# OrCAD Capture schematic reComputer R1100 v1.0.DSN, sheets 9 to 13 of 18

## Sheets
9 10 USB HUB2 & USB A: size A3
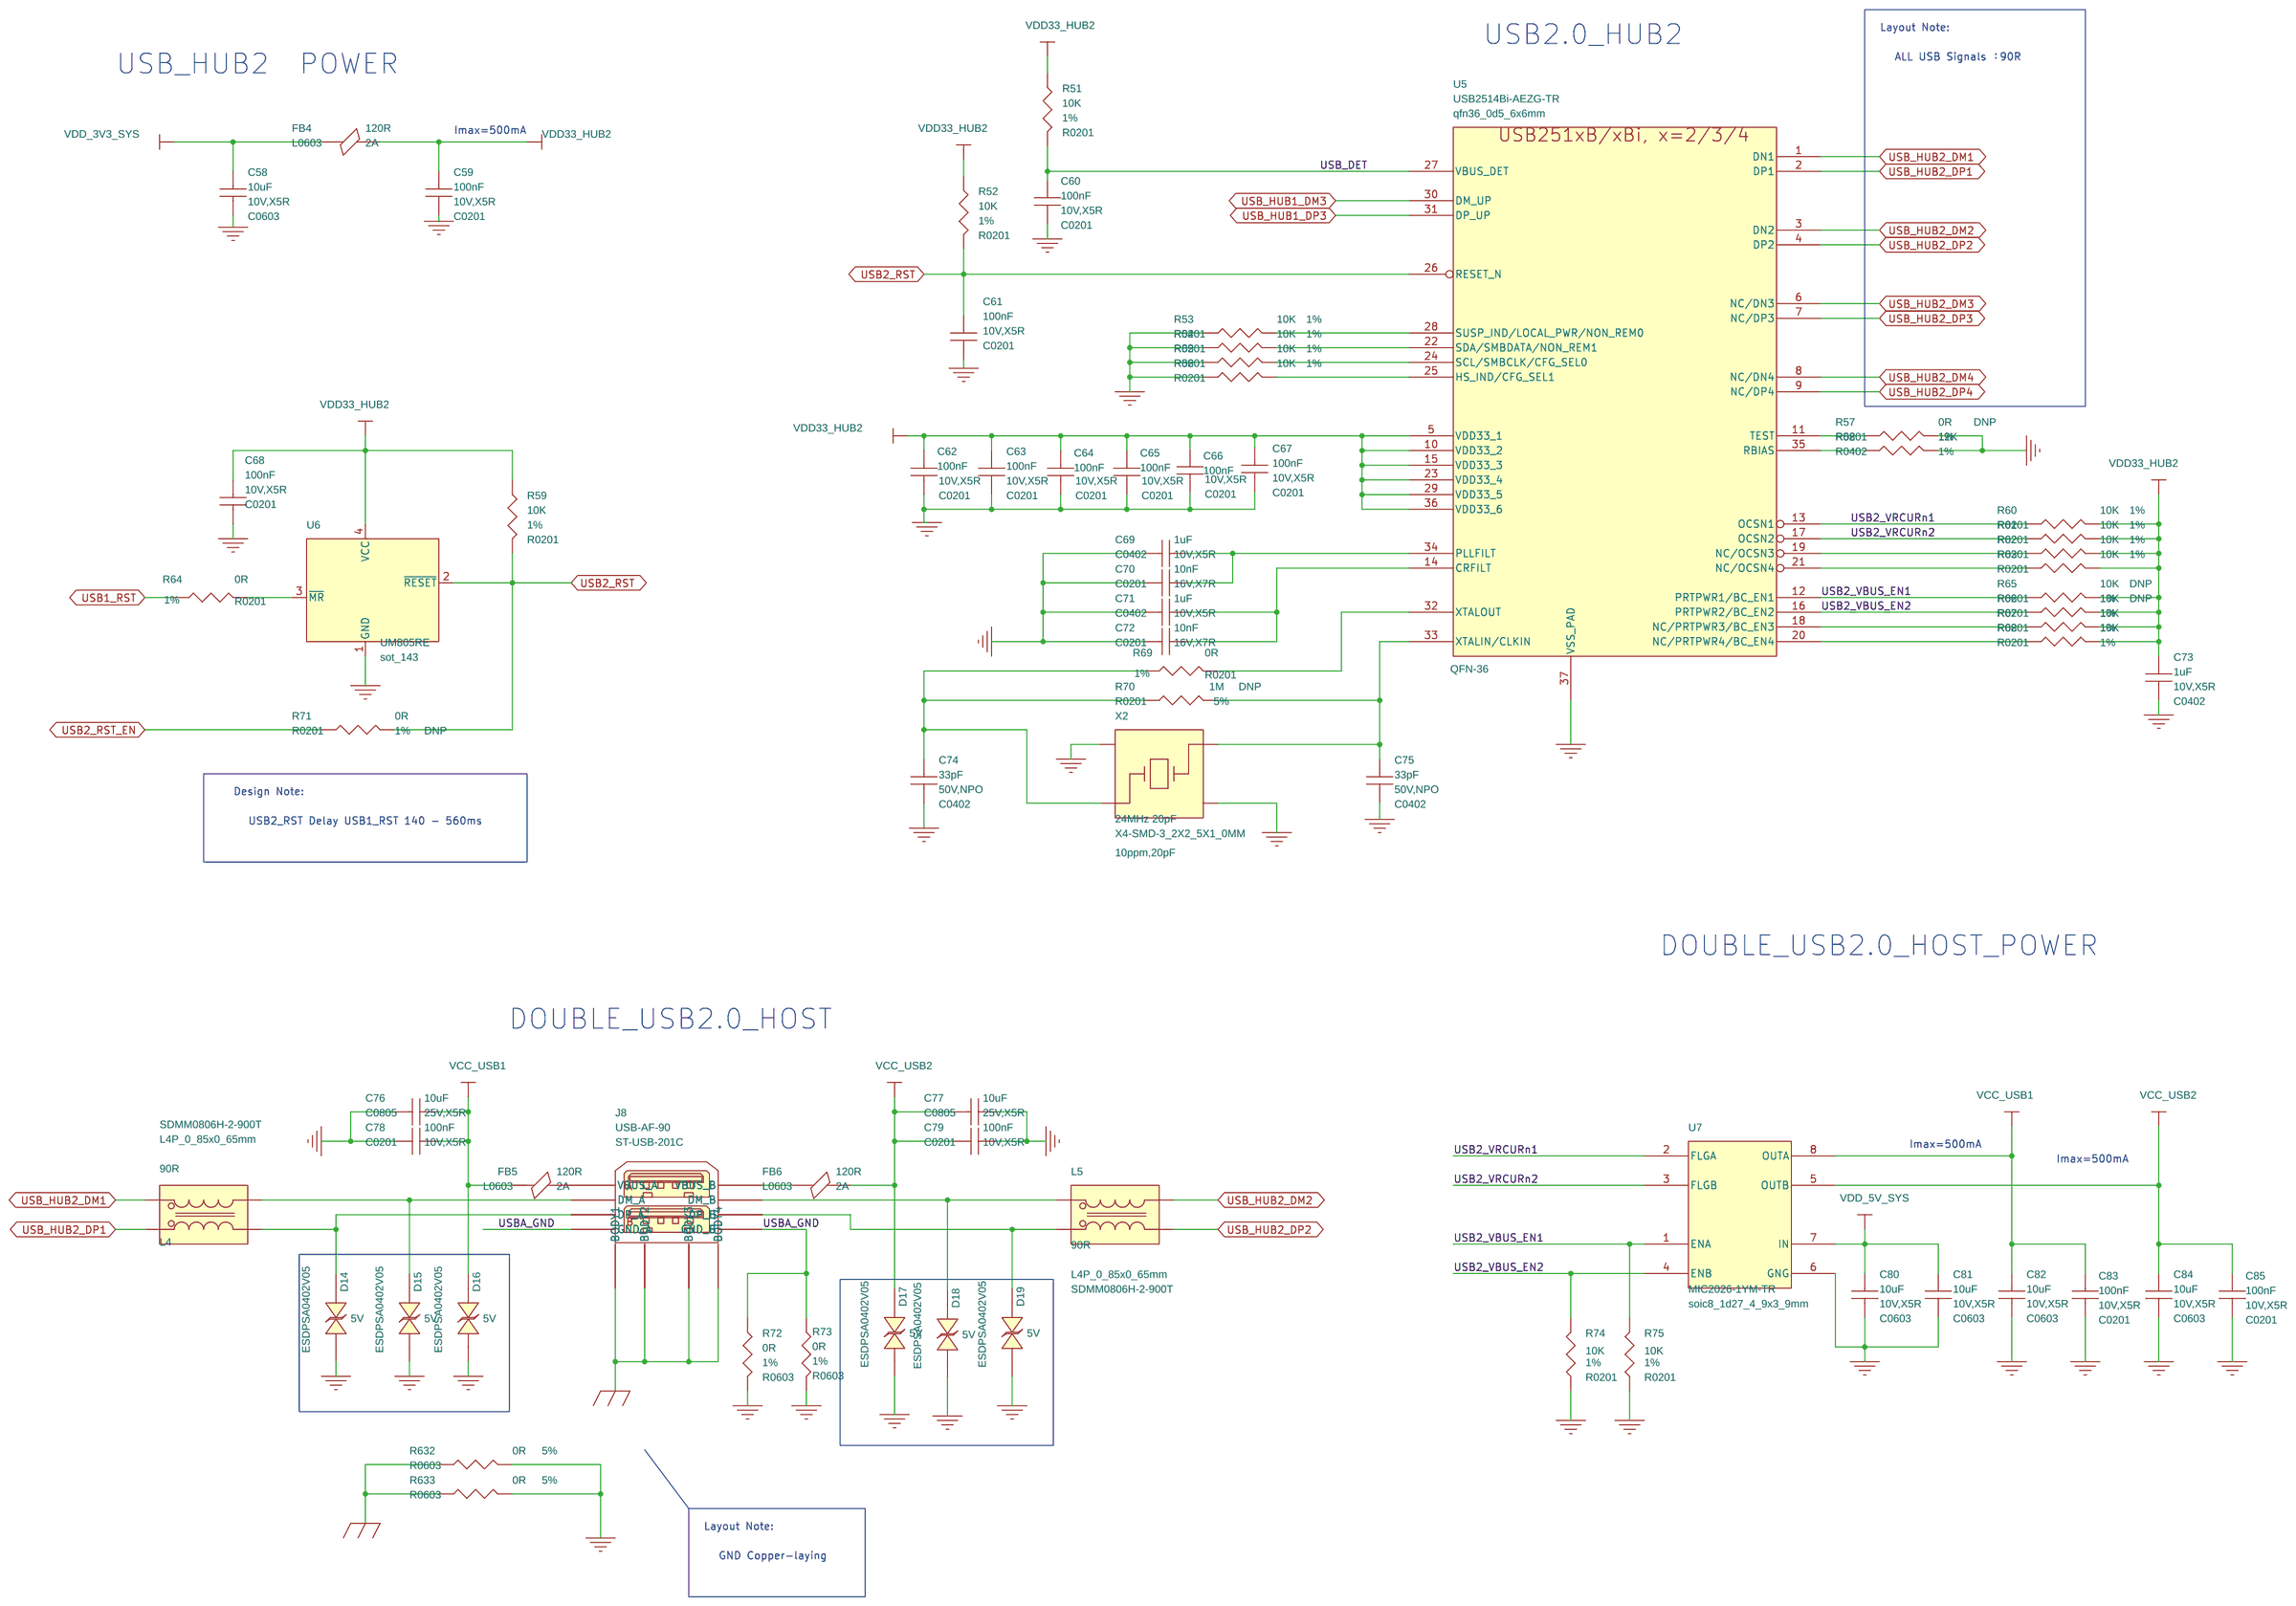
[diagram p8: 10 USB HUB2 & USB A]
10 11 HDMI & CSI0: size A3
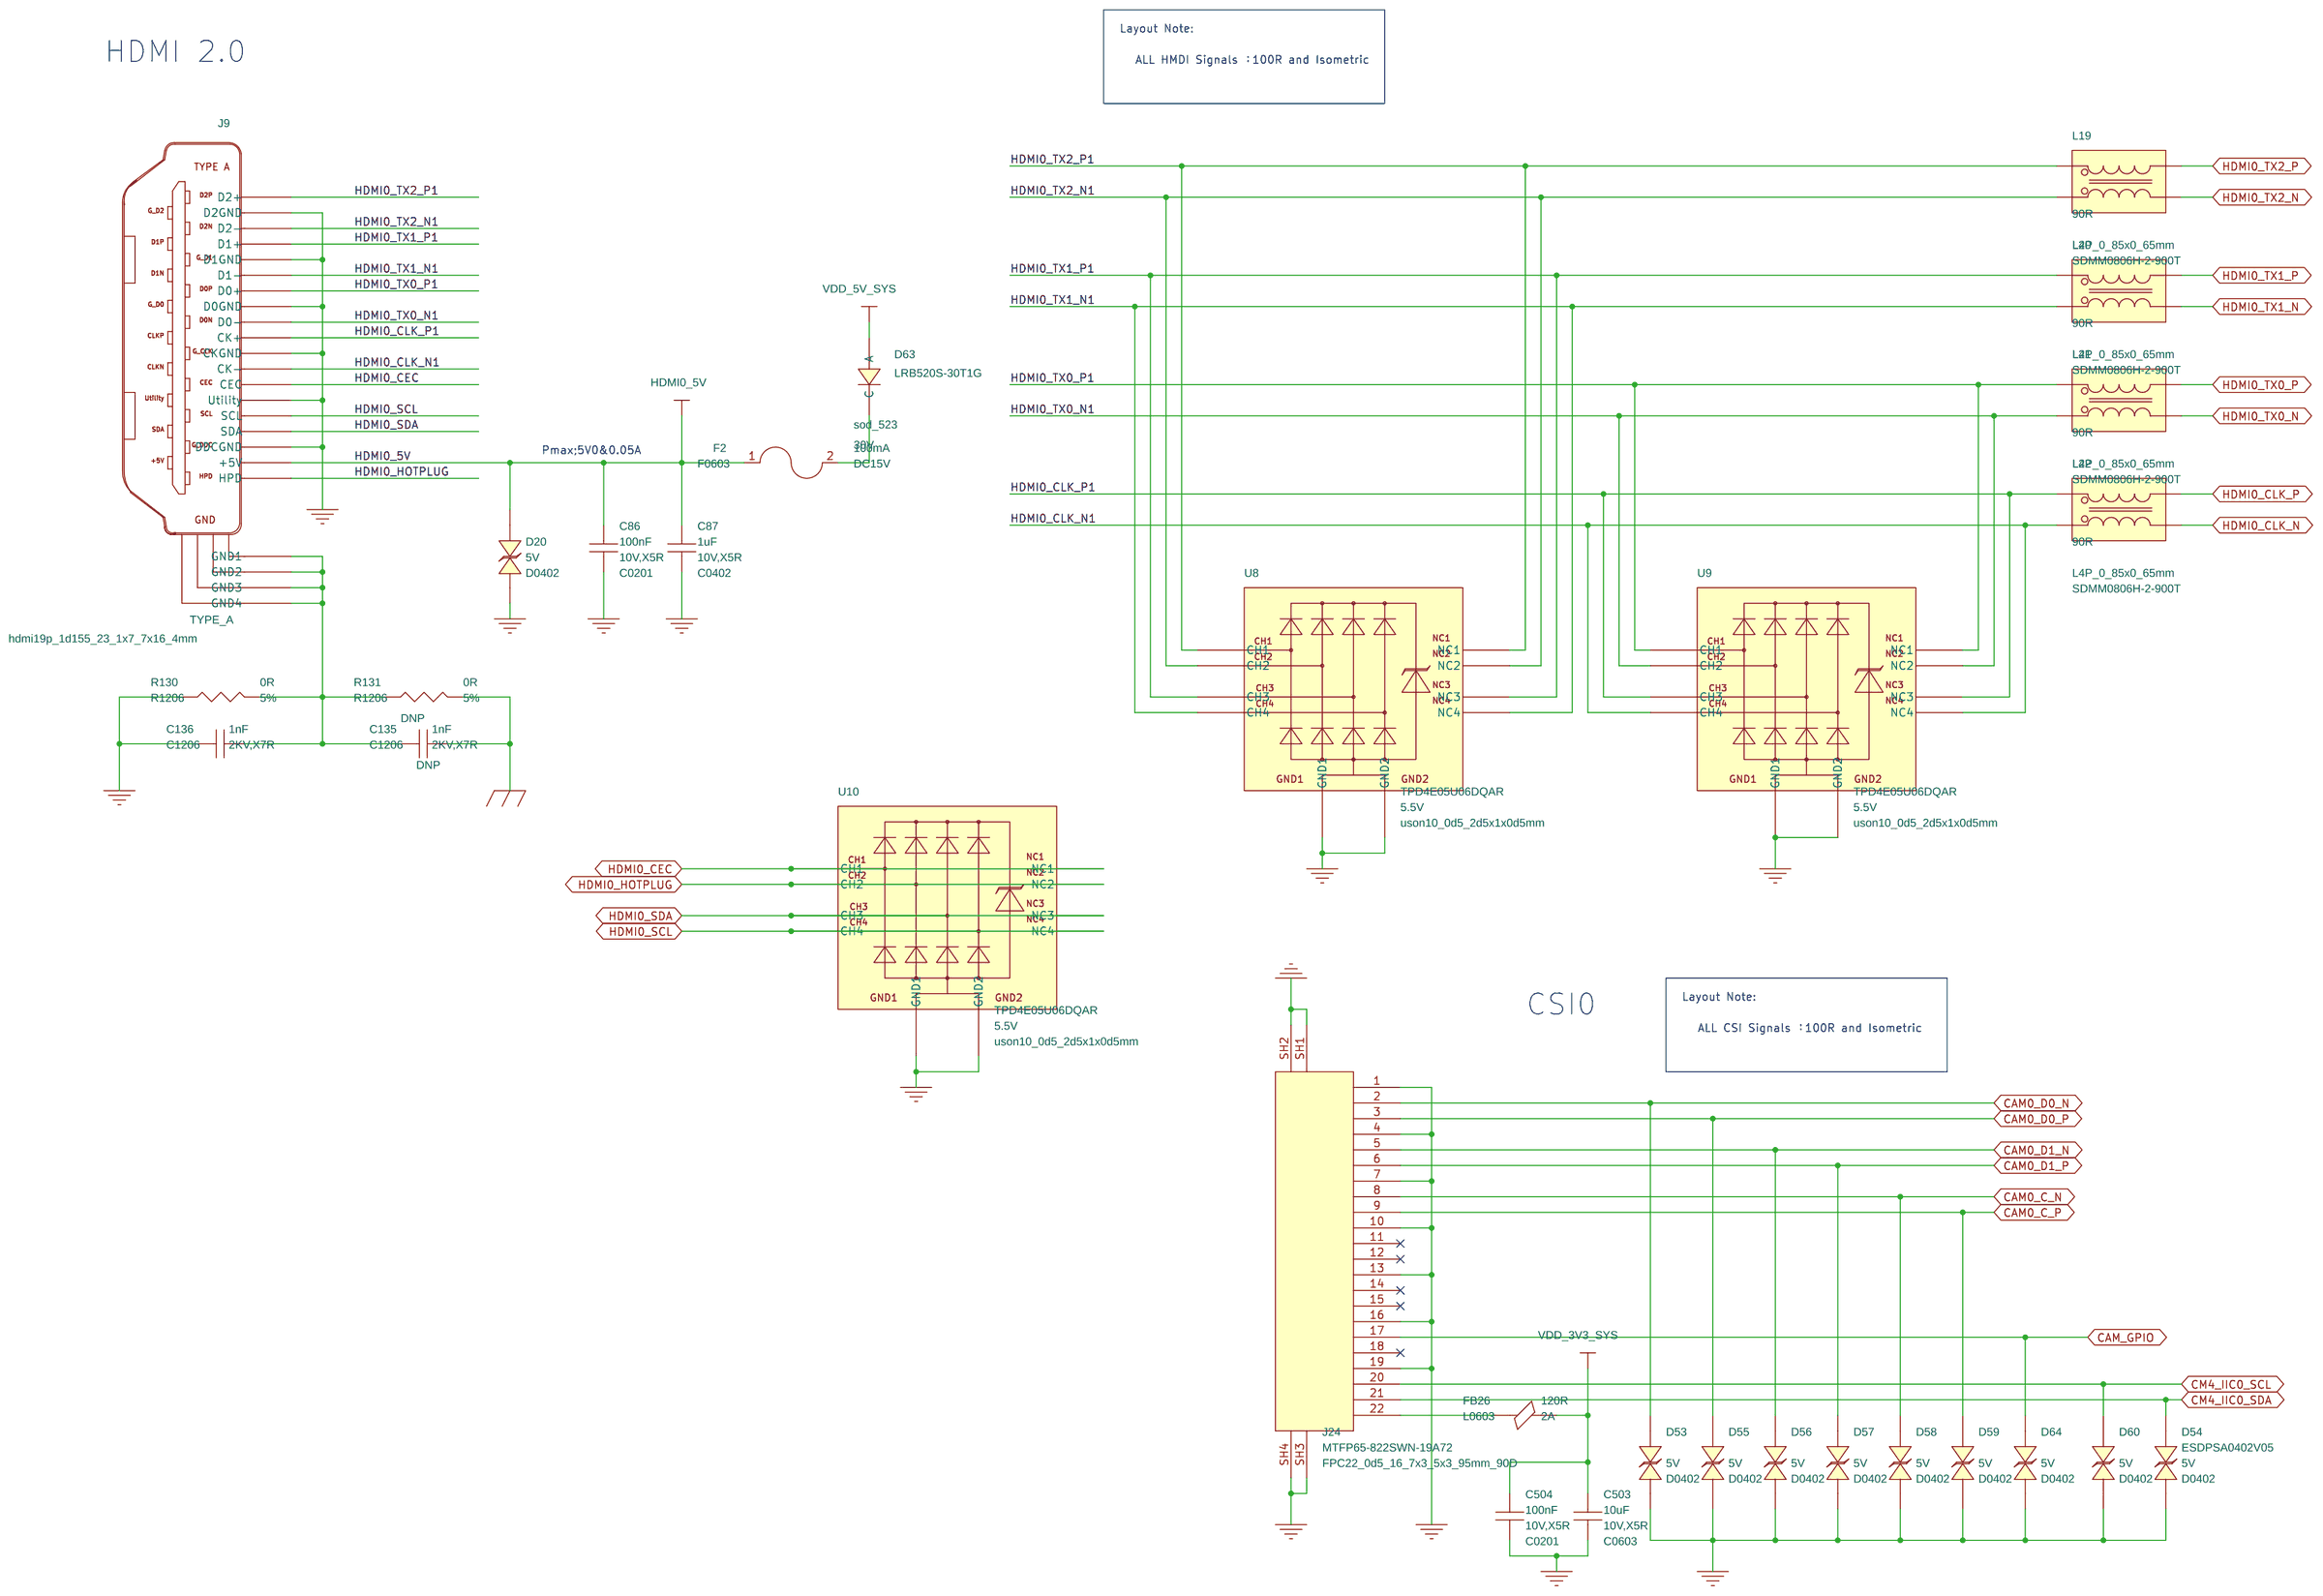
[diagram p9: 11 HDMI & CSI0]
11 13 Type-C Debug: size A3
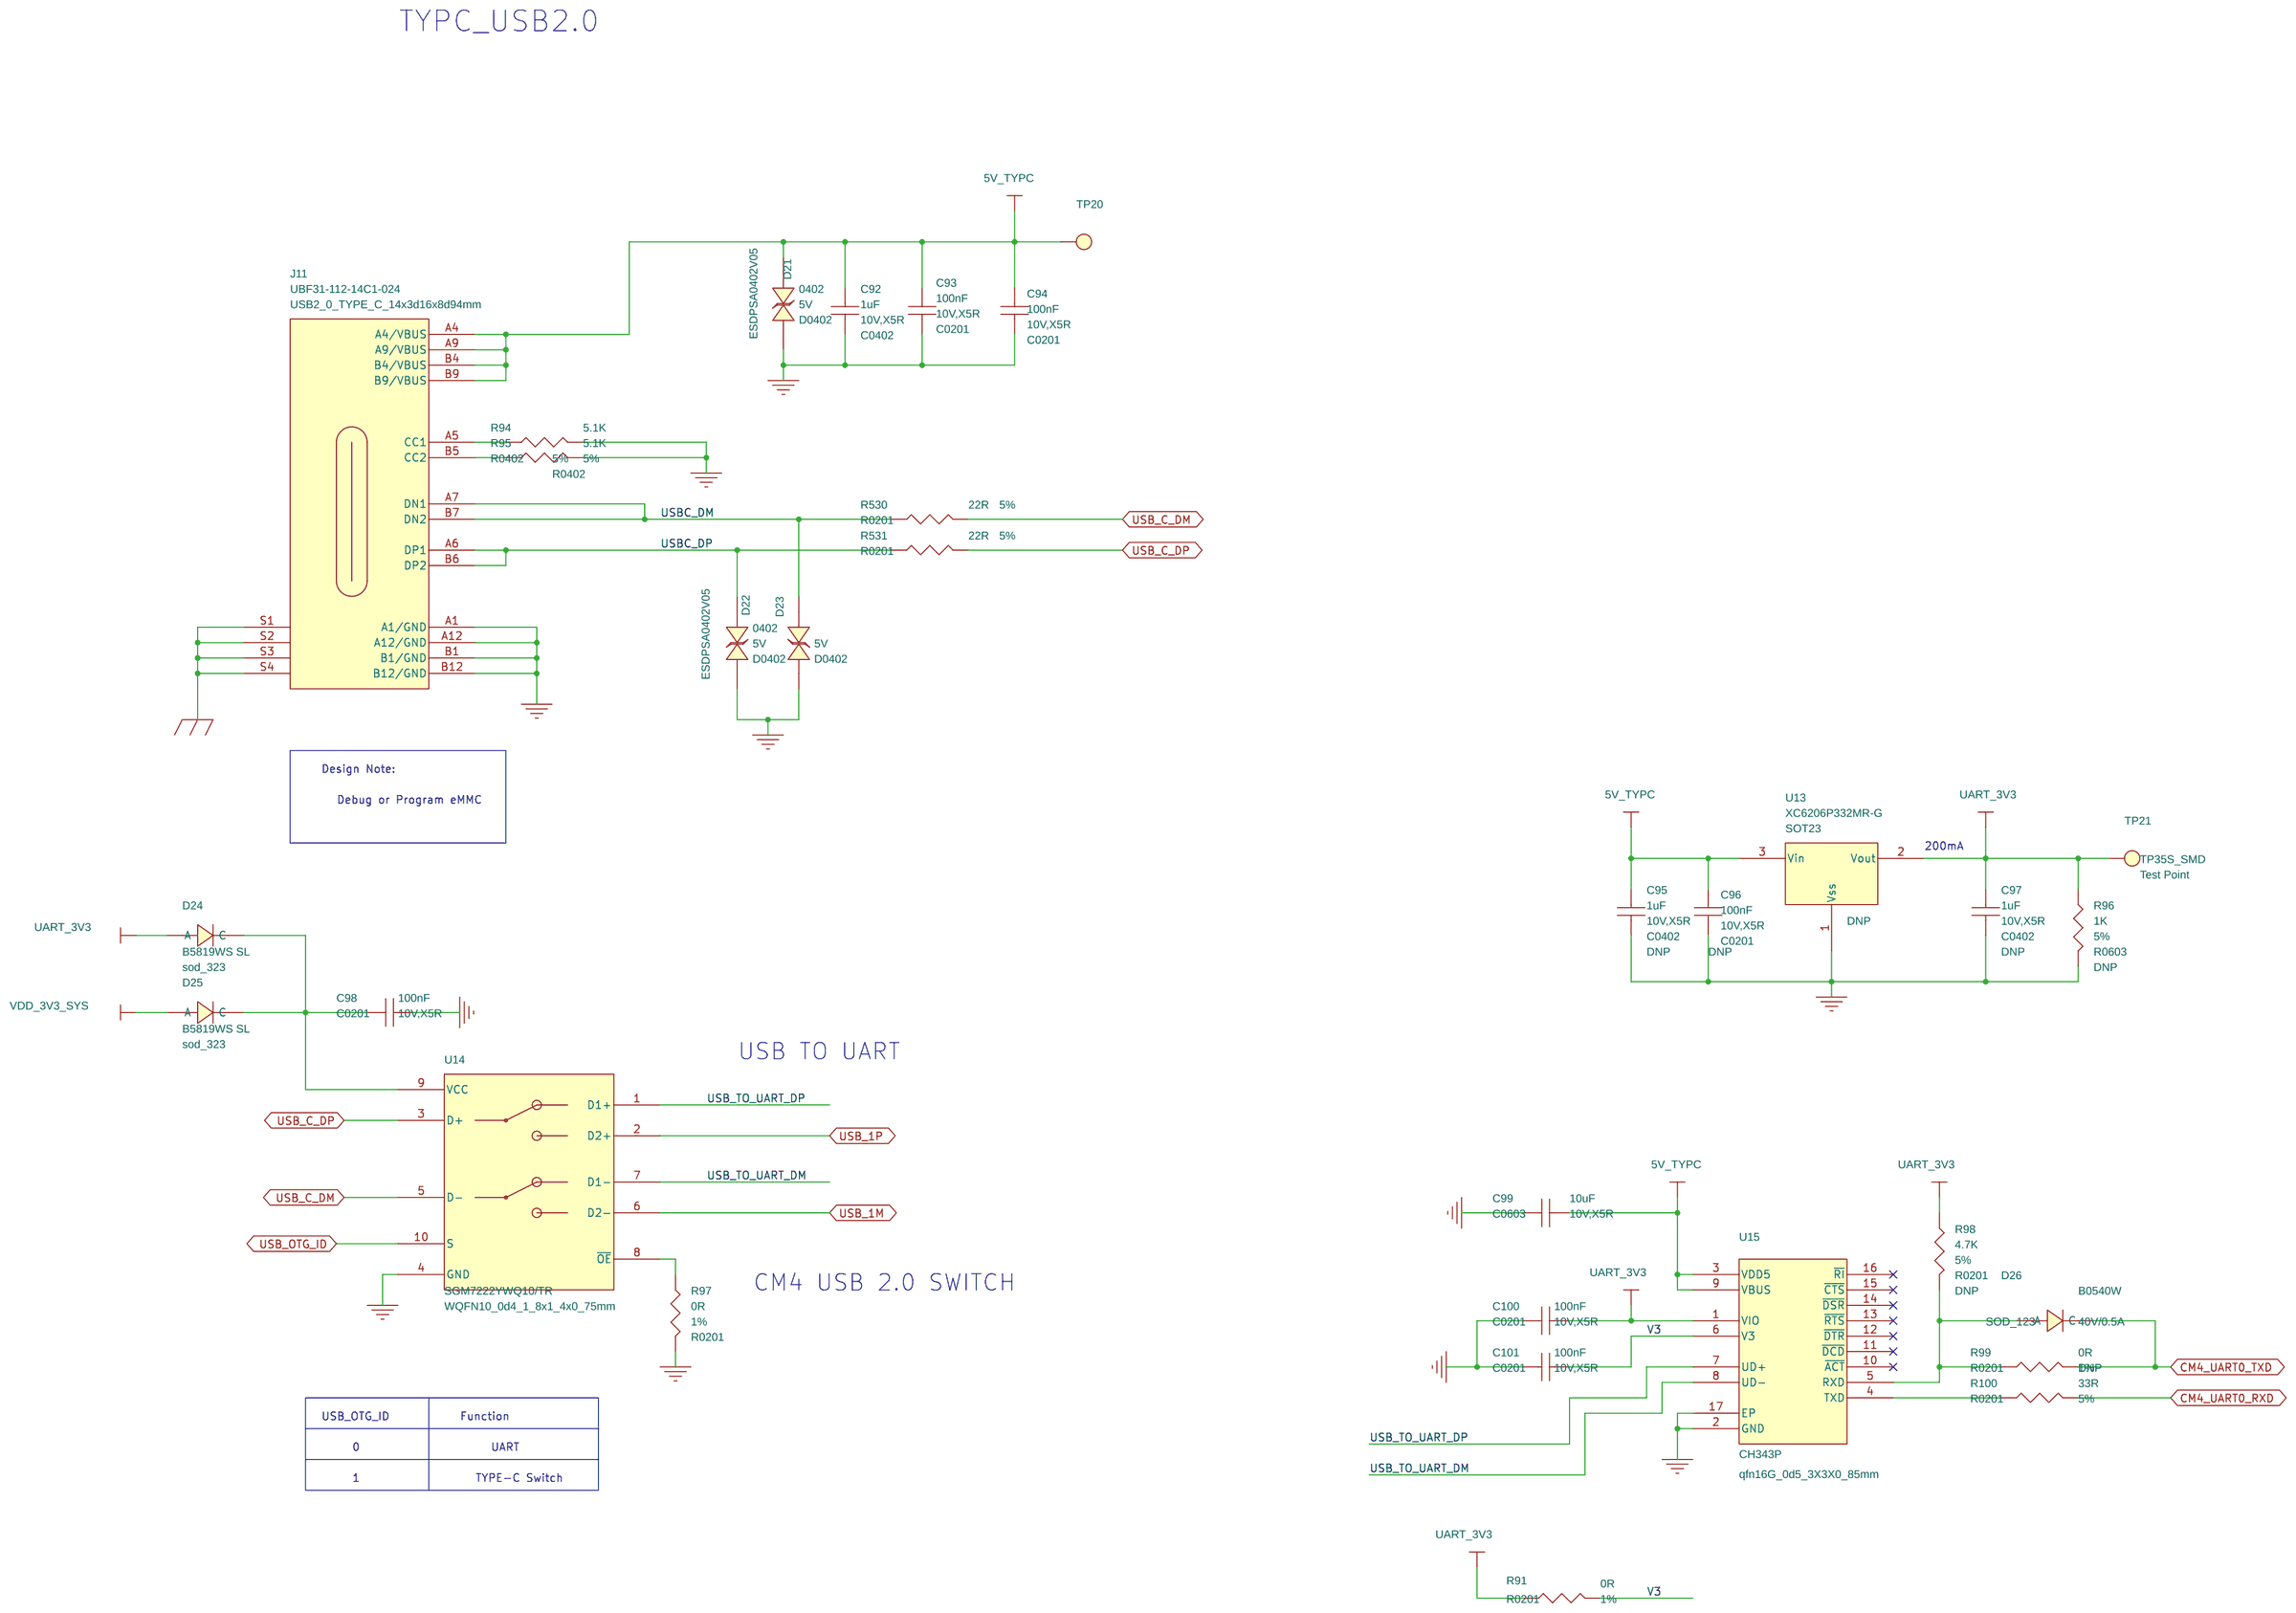
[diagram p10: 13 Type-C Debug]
12 14 RTC & Encryption & EEPROM: size A3
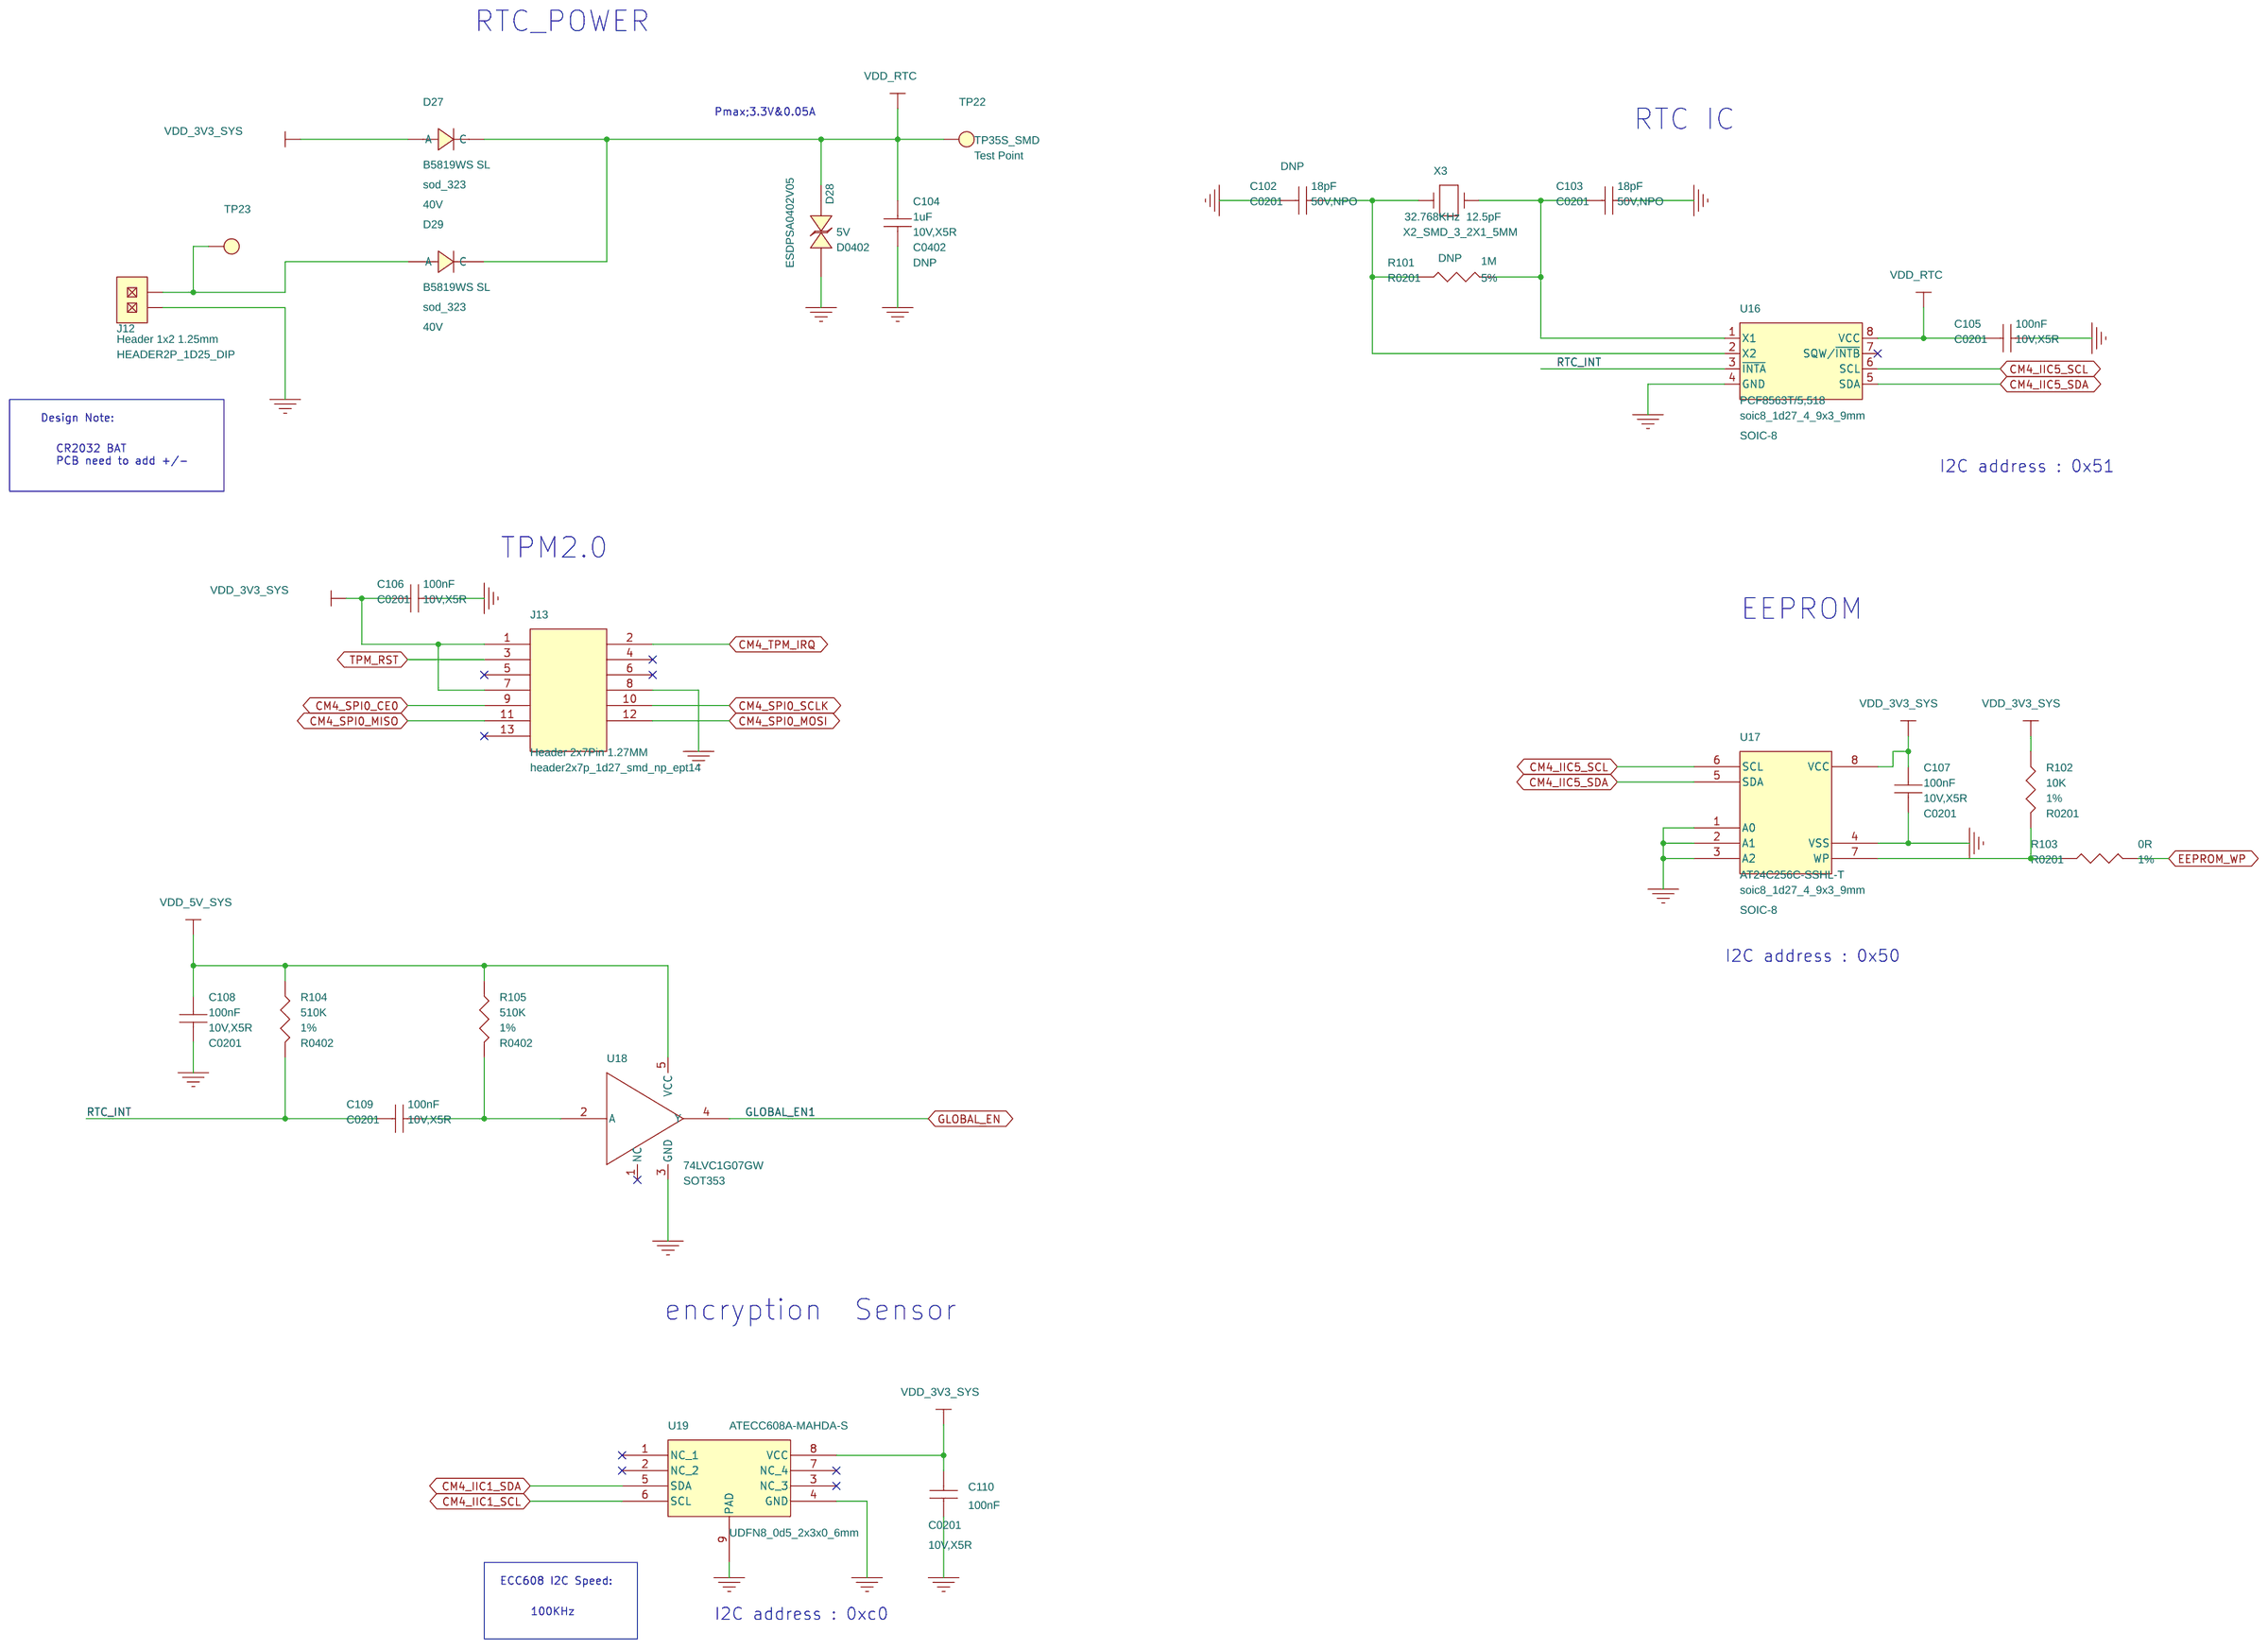
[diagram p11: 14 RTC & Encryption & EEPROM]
13 15 Mini PICe: size A3
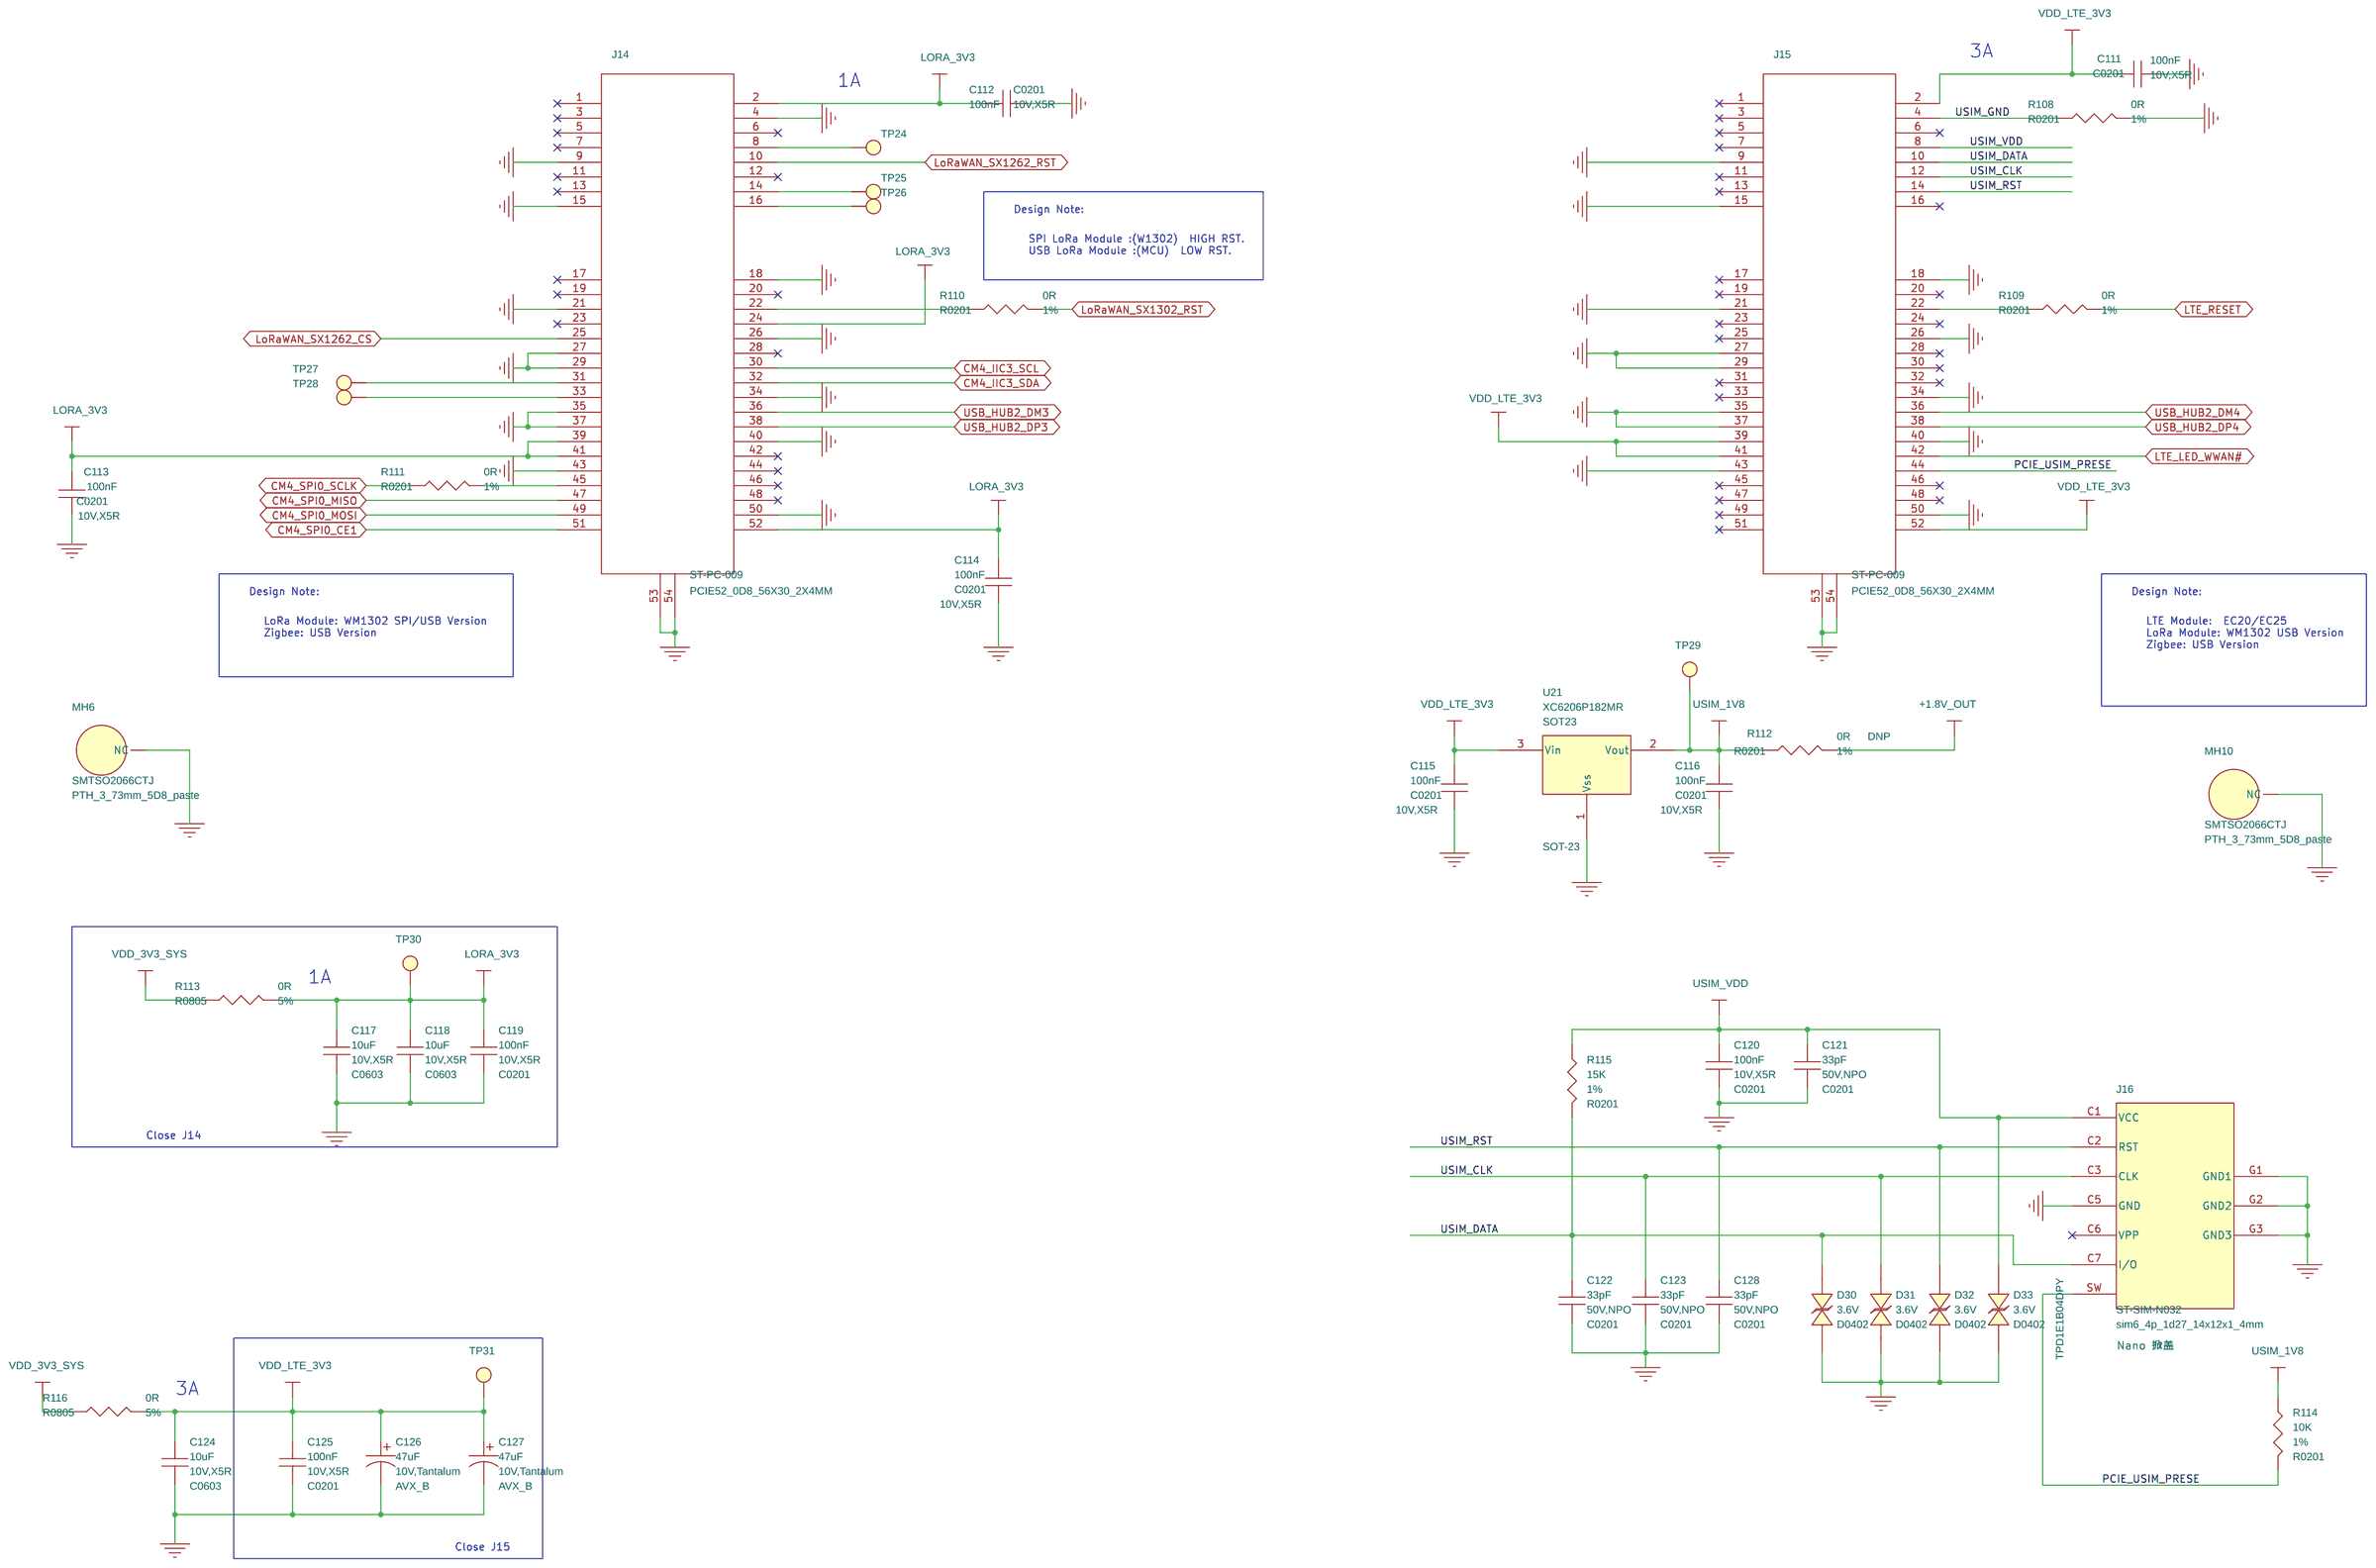
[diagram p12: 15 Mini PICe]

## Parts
sheet 10 USB HUB2 & USB A
C58  10uF  [C0603]
C59  100nF  [C0201]
C60  100nF  [C0201]
C61  100nF  [C0201]
C62  100nF  [C0201]
C63  100nF  [C0201]
C64  100nF  [C0201]
C65  100nF  [C0201]
C66  100nF  [C0201]
C67  100nF  [C0201]
C68  100nF  [C0201]
C69  1uF  [C0402]
C70  10nF  [C0201]
C71  1uF  [C0402]
C72  10nF  [C0201]
C73  1uF  [C0402]
C74  33pF  [C0402]
C75  33pF  [C0402]
C76  10uF  [C0805]
C77  10uF  [C0805]
C78  100nF  [C0201]
C79  100nF  [C0201]
C80  10uF  [C0603]
C81  10uF  [C0603]
C82  10uF  [C0603]
C83  100nF  [C0201]
C84  10uF  [C0603]
C85  100nF  [C0201]
D14  ESDPSA0402V05  [D0402]
D15  ESDPSA0402V05  [D0402]
D16  ESDPSA0402V05  [D0402]
D17  ESDPSA0402V05  [D0402]
D18  ESDPSA0402V05  [D0402]
D19  ESDPSA0402V05  [D0402]
FB4  120R  [L0603]
FB5  120R  [L0603]
FB6  120R  [L0603]
J8  USB-AF-90  [ST-USB-201C]
L4  90R  [L4P_0_85x0_65mm]
L5  90R  [L4P_0_85x0_65mm]
R51  10K  [R0201]
R52  10K  [R0201]
R53  10K  [R0201]
R54  10K  [R0201]
R55  10K  [R0201]
R56  10K  [R0201]
R57  0R  [R0201]
R58  12K  [R0402]
R59  10K  [R0201]
R60  10K  [R0201]
R61  10K  [R0201]
R62  10K  [R0201]
R63  10K  [R0201]
R64  0R  [R0201]
R65  10K  [R0201]
R66  10K  [R0201]
R67  10K  [R0201]
R68  10K  [R0201]
R69  0R  [R0201]
R70  1M  [R0201]
R71  0R  [R0201]
R72  0R  [R0603]
R73  0R  [R0603]
R74  10K  [R0201]
R75  10K  [R0201]
R632  0R  [R0603]
R633  0R  [R0603]
U5  USB2514Bi-AEZG-TR  [qfn36_0d5_6x6mm]
U6  UM805RE  [sot_143]
U7  MIC2026-1YM-TR  [soic8_1d27_4_9x3_9mm]
X2  24MHz 20pF  [X4-SMD-3_2X2_5X1_0MM]
sheet 11 HDMI & CSI0
C86  100nF  [C0201]
C87  1uF  [C0402]
C135  1nF  [C1206]
C136  1nF  [C1206]
C503  10uF  [C0603]
C504  100nF  [C0201]
D20  ESDPSA0402V05  [D0402]
D53  ESDPSA0402V05  [D0402]
D54  ESDPSA0402V05  [D0402]
D55  ESDPSA0402V05  [D0402]
D56  ESDPSA0402V05  [D0402]
D57  ESDPSA0402V05  [D0402]
D58  ESDPSA0402V05  [D0402]
D59  ESDPSA0402V05  [D0402]
D60  ESDPSA0402V05  [D0402]
D63  LRB520S-30T1G  [sod_523]
D64  ESDPSA0402V05  [D0402]
F2  100mA  [F0603]
FB26  120R  [L0603]
J9  TYPE_A  [hdmi19p_1d155_23_1x7_7x16_4mm]
J24  MTFP65-822SWN-19A72  [FPC22_0d5_16_7x3_5x3_95mm_90D]
L19  90R  [L4P_0_85x0_65mm]
L20  90R  [L4P_0_85x0_65mm]
L21  90R  [L4P_0_85x0_65mm]
L22  90R  [L4P_0_85x0_65mm]
R130  0R  [R1206]
R131  0R  [R1206]
U8  TPD4E05U06DQAR  [uson10_0d5_2d5x1x0d5mm]
U9  TPD4E05U06DQAR  [uson10_0d5_2d5x1x0d5mm]
U10  TPD4E05U06DQAR  [uson10_0d5_2d5x1x0d5mm]
sheet 13 Type-C Debug
C92  1uF  [C0402]
C93  100nF  [C0201]
C94  100nF  [C0201]
C95  1uF  [C0402]
C96  100nF  [C0201]
C97  1uF  [C0402]
C98  100nF  [C0201]
C99  10uF  [C0603]
C100  100nF  [C0201]
C101  100nF  [C0201]
D21  ESDPSA0402V05  [D0402]
D22  ESDPSA0402V05  [D0402]
D23  ESDPSA0402V05  [D0402]
D24  B5819WS SL  [sod_323]
D25  B5819WS SL  [sod_323]
D26  B0540W  [SOD_123]
J11  UBF31-112-14C1-024  [USB2_0_TYPE_C_14x3d16x8d94mm]
R91  0R  [R0201]
R94  5.1K  [R0402]
R95  5.1K  [R0402]
R96  1K  [R0603]
R97  0R  [R0201]
R98  4.7K  [R0201]
R99  0R  [R0201]
R100  33R  [R0201]
R530  22R  [R0201]
R531  22R  [R0201]
TP20  Test Point  [TP35S_SMD]
TP21  Test Point  [TP35S_SMD]
U13  XC6206P332MR-G  [SOT23]
U14  SGM7222YWQ10/TR  [WQFN10_0d4_1_8x1_4x0_75mm]
U15  CH343P  [qfn16G_0d5_3X3X0_85mm]
sheet 14 RTC & Encryption & EEPROM
C102  18pF  [C0201]
C103  18pF  [C0201]
C104  1uF  [C0402]
C105  100nF  [C0201]
C106  100nF  [C0201]
C107  100nF  [C0201]
C108  100nF  [C0201]
C109  100nF  [C0201]
C110  100nF  [C0201]
D27  B5819WS SL  [sod_323]
D28  ESDPSA0402V05  [D0402]
D29  B5819WS SL  [sod_323]
J12  Header 1x2 1.25mm  [HEADER2P_1D25_DIP]
J13  Header 2x7Pin 1.27MM  [header2x7p_1d27_smd_np_ept14]
R101  1M  [R0201]
R102  10K  [R0201]
R103  0R  [R0201]
R104  510K  [R0402]
R105  510K  [R0402]
TP22  Test Point  [TP35S_SMD]
TP23  Test Point  [TP35S_SMD]
U16  PCF8563T/5,518  [soic8_1d27_4_9x3_9mm]
U17  AT24C256C-SSHL-T  [soic8_1d27_4_9x3_9mm]
U18  74LVC1G07GW  [SOT353]
U19  ATECC608A-MAHDA-S  [UDFN8_0d5_2x3x0_6mm]
X3  32.768KHz  12.5pF  [X2_SMD_3_2X1_5MM]
sheet 15 Mini PICe
C111  100nF  [C0201]
C112  100nF  [C0201]
C113  100nF  [C0201]
C114  100nF  [C0201]
C115  100nF  [C0201]
C116  100nF  [C0201]
C117  10uF  [C0603]
C118  10uF  [C0603]
C119  100nF  [C0201]
C120  100nF  [C0201]
C121  33pF  [C0201]
C122  33pF  [C0201]
C123  33pF  [C0201]
C124  10uF  [C0603]
C125  100nF  [C0201]
C126  47uF  [AVX_B]
C127  47uF  [AVX_B]
C128  33pF  [C0201]
D30  TPD1E1B04DPY  [D0402]
D31  TPD1E1B04DPY  [D0402]
D32  TPD1E1B04DPY  [D0402]
D33  TPD1E1B04DPY  [D0402]
J14  ST-PC-009  [PCIE52_0D8_56X30_2X4MM]
J15  ST-PC-009  [PCIE52_0D8_56X30_2X4MM]
J16  ST-SIM-N032  [sim6_4p_1d27_14x12x1_4mm]
MH6  SMTSO2066CTJ  [PTH_3_73mm_5D8_paste]
MH10  SMTSO2066CTJ  [PTH_3_73mm_5D8_paste]
R108  0R  [R0201]
R109  0R  [R0201]
R110  0R  [R0201]
R111  0R  [R0201]
R112  0R  [R0201]
R113  0R  [R0805]
R114  10K  [R0201]
R115  15K  [R0201]
R116  0R  [R0805]
TP24  Test Point  [TP35S_SMD]
TP25  Test Point  [TP35S_SMD]
TP26  Test Point  [TP35S_SMD]
TP27  Test Point  [TP35S_SMD]
TP28  Test Point  [TP35S_SMD]
TP29  Test Point  [TP35S_SMD]
TP30  Test Point  [TP35S_SMD]
TP31  Test Point  [TP35S_SMD]
U21  XC6206P182MR  [SOT23]

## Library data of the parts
C58 = CC: SMD CAP Ceramic 10uF-10V-10%-X5R;0603; CLASS: DISCRETE; Company Part Status: BeagleBone Carrier Board; Dielectric Type: Ceramic; Manufacturer: YAGEO; Manufacturer PN: CC0603KRX5R6BB106; Manufacturer Part Number: CC0603KRX5R6BB106; PN: 302010103; Package Size: 0603; Part Type: Ceramic; Rating: 10V,X5R; Status: BeagleBone Carrier Board; Temperature: -55°C to 85°C; Temperature Coefficient: X5R; Tolerance: 10%
C59-C68 C83 C85 C93 C94 C98 C100 C101 C111 C119 C125 C504 = CC: SMD CAP Ceramic 100nF-10V-10%-X5R;0201; CLASS: DISCRETE; Company Part Status: BeagleBone Carrier Board; Dielectric Type: Ceramic; Manufacturer: YAGEO; Manufacturer PN: CC0402KRX7R8BB104; Manufacturer Part Number: CC0201KRX5R6BB104; PN: 302010271; Package Size: 0201; Part Type: Ceramic; Rating: 10V,X5R; SIGNAL_MODEL: DEFAULT_CAPACITOR_100000pF_1_2; Status: ODYSSEY-i.MX8M; Temperature: -55°C to 85°C; Temperature Coefficient: X7R; Tolerance: 10%
C69 C71 C73 = CC: SMD CAP Ceramic 1uF-10V-10%-X5R;0402; CLASS: DISCRETE; Company Part Status: BeagleBone Carrier Board; Dielectric Type: Ceramic; Manufacturer: YAGEO; Manufacturer PN: CC0402KRX5R6BB105; Manufacturer Part Number: CC0402KRX5R6BB105; PN: 302010040; Package Size: 0402; Part Type: Ceramic; Rating: 10V,X5R; Status: BeagleBone Carrier Board; Temperature: -55°C to 85°C; Temperature Coefficient: X5R; Tolerance: 10%
C70 C72 = CC: SMD CAP Ceramic 10nF-16V-10%-X7R;0201; CLASS: DISCRETE; Company Part Status: BeagleBone Carrier Board; Dielectric Type: Ceramic; Manufacturer: YAGEO; Manufacturer PN: CC0402KRX7R9BB103; Manufacturer Part Number: CC0201KRX7R7BB103; PN: 302010431; Part Type: Ceramic; Rating: 16V,X7R; SIGNAL_MODEL: DEFAULT_CAPACITOR_10000pF_1_2; Status: BeagleBone AI TDA4VM; Temperature: -55°C to 125°C; Temperature Coefficient: X7R; Tolerance: 10%
C74 C75 = CC: SMD CAP Ceramic 33pF-50V-1%-NPO;0402; Manufacturer: Murata; Manufacturer Part Number: GRM1555C1H330FA01D; PN: 302012253; Package Size: 0402; Rating: 50V,NPO; Status: reComputer R1000; Temperature: -55°C to 125°C
C76 C77 = CC: SMD CAP Ceramic 10uF-25V-10%-X5R;0805; CLASS: DISCRETE; Dielectric Type: Ceramic; Manufacturer: YAGEO; Manufacturer PN: CC0603MRX5R6BB226; Manufacturer Part Number: CC0805KKX5R8BB106; PN: 302010178; Package Size: 0603; Part Type: Ceramic; Rating: 25V,X5R; Status: BeagleBone Carrier Board; Temperature: -55°C to 85°C; Temperature Coefficient: X5R; Tolerance: 20%
C78 C79 = CC: SMD CAP Ceramic 100nF-10V-10%-X5R;0201; CLASS: DISCRETE; Company Part Status: BeagleBone Carrier Board; Dielectric Type: Ceramic; Manufacturer: YAGEO; Manufacturer PN: CC0402KRX7R8BB104; Manufacturer Part Number: CC0201KRX5R6BB104; PN: 302010271; Package Size: 0201; Part Type: Ceramic; Rating: 10V,X5R; Status: ODYSSEY-i.MX8M; Temperature: -55°C to 85°C; Temperature Coefficient: X7R; Tolerance: 10%
C80-C82 C84 C99 C117 C118 C124 = CC: SMD CAP Ceramic 10uF-10V-10%-X5R;0603; CLASS: DISCRETE; Dielectric Type: Ceramic; Manufacturer: YAGEO; Manufacturer PN: CC0603MRX5R6BB226; Manufacturer Part Number: CC0603KRX5R6BB106; PN: 302010103; Package Size: 0603; Part Type: Ceramic; Rating: 10V,X5R; Status: BeagleBone Carrier Board; Temperature: -55°C to 85°C; Temperature Coefficient: X5R; Tolerance: 20%
D14-D23 D28 = DIODE_TVS_BI-DIR: SMD Diode ESD 0.05pF;0402; CLASS: DISCRETE; Company Part Status: BeagleBone Carrier Board; Manufacturer: SEMITEL; PN: 304060074; Package Size: 0402; Part Type: TVS; Rated Voltage: 5V; Rating: 5V; Status: BeagleBone Carrier Board; Temperature: -40°C to 90°C
FB4-FB6 FB26 = FB: SMD Ferrite Bead;120R-2A;0603; CLASS: DISCRETE; Company Part Status: BeagleBone Carrier Board; Manufacturer: Murata; Manufacturer PN: BLM18PG121SN1D; Manufacturer Part Number: BLM18PG121SN1D; PN: 303030024; Package Size: 0603; Part Type: Ferrite Bead; Rating: 2A; Status: BeagleBone Carrier Board; Temperature: -55°C to 125°C
J8 = Dual_USB_A: DIP USB FEMAL TYPE A;8P-2.0-90D; Manufacturer: 宇亮; PN: 320010475; Part Type: USB; Status: BeagleBone Carrier Board
L4 L5 L19-L22 = CL: SMD Common Mode Filter 90R-100mA;4P-L0.85*W0.65*H0.40mm; Manufacturer: Sunlord; Manufacturer Part Number: SDMM0806H-2-900T; PN: 303050463; Package Size: 0.85x0.65 mm; Status: BeaglePlay; Temperature: -40°C to 85°C
R51-R56 R59 R102 = R: SMD RES 10K-±1%-1/20W;0201; CLASS: DISCRETE; Company Part Status: BeagleBone Carrier Board; Manufacturer: YAGEO; Manufacturer PN: RC0402JR-0710KL; Manufacturer Part Number: RC0201FR-0710KL; PN: 301010526; Package Size: 0201; Part Type: RES; Rated Power: 1/16W; Rating: 1%; Status: BeagleBone AI TDA4VM; Temperature: -55°C to 125°C
R57 R112 = R: SMD RES 0R-±1%-1/20W;0201; ASSY: DNP; CLASS: DISCRETE; Company Part Status: BeagleBone Carrier Board; Manufacturer: YAGEO; Manufacturer PN: RC0402JR-070RL; Manufacturer Part Number: RC0201FR-070RL; PN: 301010525; Package Size: 0201; Part Type: RES; Rated Power: 1/16W; Rating: 1%; SIGNAL_MODEL: DEFAULT_RESISTOR_0.001OHM_1_2; Status: BeagleBone AI TDA4VM; Temperature: -55°C to 125°C; Datasheet: Y:\01_Cadence_Library\05_Datasheet\301010000_YAGEO_RC0402JR-070RL_Datasheet.pdf
R58 = R: SMD RES 12K-1%-1/16W;0402; CLASS: DISCRETE; Company Part Status: BeagleBone Carrier Board; Manufacturer: YAGEO; Manufacturer PN: RC0402FR-0712KL; Manufacturer Part Number: RC0402FR-0712KL; PN: 301010736; Package Size: 0402; Part Type: RES; Rated Power: 1/16W; Rating: 1%; SIGNAL_MODEL: DEFAULT_RESISTOR_12000OHM_1_2; Status: BeagleBone Carrier Board; Temperature: -55°C to 155°C
R60-R63 R67 R68 R74 R75 = R: SMD RES 10K-±1%-1/20W;0201; CLASS: DISCRETE; Company Part Status: BeagleBone Carrier Board; Manufacturer: YAGEO; Manufacturer PN: RC0402JR-0710KL; Manufacturer Part Number: RC0201FR-0710KL; PN: 301010526; Package Size: 0201; Part Type: RES; Rated Power: 1/16W; Rating: 1%; SIGNAL_MODEL: DEFAULT_RESISTOR_10000OHM_1_2; Status: BeagleBone AI TDA4VM; Temperature: -55°C to 125°C
R64 R69 R103 = R: SMD RES 0R-±1%-1/20W;0201; CLASS: DISCRETE; Company Part Status: BeagleBone Carrier Board; Manufacturer: YAGEO; Manufacturer PN: RC0402JR-070RL; Manufacturer Part Number: RC0201FR-070RL; PN: 301010525; Package Size: 0201; Part Type: RES; Rated Power: 1/16W; Rating: 1%; Status: BeagleBone AI TDA4VM; Temperature: -55°C to 125°C; Datasheet: Y:\01_Cadence_Library\05_Datasheet\301010000_YAGEO_RC0402JR-070RL_Datasheet.pdf
R65 R66 = R: SMD RES 10K-±1%-1/20W;0201; ASSY: DNP; CLASS: DISCRETE; Company Part Status: BeagleBone Carrier Board; Manufacturer: YAGEO; Manufacturer PN: RC0402JR-0710KL; Manufacturer Part Number: RC0201FR-0710KL; PN: 301010526; Package Size: 0201; Part Type: RES; Rated Power: 1/16W; Rating: 1%; SIGNAL_MODEL: DEFAULT_RESISTOR_10000OHM_1_2; Status: BeagleBone AI TDA4VM; Temperature: -55°C to 125°C
R70 = R: SMD RES 1M-5%-1/20W;0201; ASSY: DNP; CLASS: DISCRETE; Company Part Status: BeagleBone Carrier Board; Manufacturer: YAGEO; Manufacturer PN: RC0402FR-071ML; Manufacturer Part Number: RC0201JR-071ML; PN: 301010676; Package Size: 0201; Part Type: RES; Rated Power: 1/16W; Rating: 5%; SIGNAL_MODEL: DEFAULT_RESISTOR_0.001OHM_1_2; Status: BeagleV-Ahead; Temperature: -55°C to 155°C
R71 R99 = R: SMD RES 0R-±1%-1/20W;0201; ASSY: DNP; Manufacturer: YAGEO; Manufacturer Part Number: RC0201FR-070RL; PN: 301010525; Package Size: 0201; Part Type: RES; Rating: 1%; Status: BeagleBone AI TDA4VM; Temperature: -55°C to 125°C; Datasheet: Y:\01_Cadence_Library\05_Datasheet\301010000_YAGEO_RC0402JR-070RL_Datasheet.pdf
R72 R73 = R: SMD RES 0R-1%-1/10W;0603; CLASS: DISCRETE; Manufacturer: YAGEO; Manufacturer PN: RC0603JR-070RL; Manufacturer Part Number: RC0603FR-070RL; PN: 301012029; Package Size: 0603; Part Type: RES; Rated Power: 1/10W; Rating: 1%; Status: BBG Gateway; Temperature: -55°C to 155°C
R632 R633 = R: SMD RES 0R-5%-1/10W;0603; Manufacturer: YAGEO; Manufacturer Part Number: RC0603JR-070RL; PN: 301010292; Part Type: RES; Rating: 5%; Temperature: -55°C to 155°C
U5 = USB251xB_xBi: SMD IC USB CONTROLLER;QFN-36; CLASS: IC; Company Part Status: Sensecap Gateway V2; Manufacturer: Microchip; PN: 310990577; Package Size: QFN-36; Part Type: USB Hub; Rating: USB 2.0 Hub; Status: Sensecap Gateway V2; Temperature: -40°C to 85°C
U6 = UM805_4P: SMD IC PMIC;Reset Circuit;2.63V VTH RST;SOT143; Manufacturer: Union Semiconductor; PN: 310031538; Part Type: Reset IC; Status: RT-M7
U7 = MIC2026: SMD IC PMIC;SWITCH-2CH;SOIC-8; Manufacturer: Microchip; PN: 310031315; Part Type: Power Switch; Status: BeagleBone Carrier Board
X2 = XTAL_4P: SMD Crystal 24MHz-20pF-10ppm;4P-SMD-L3.2*W2.5*H0.7mm; Manufacturer: 东晶电子; Manufacturer Part Number: M24000J407; PN: 306011544; Package Size: 3.2x2.5x0.7mm; Rating: 10ppm,20pF; Status: J40 MINI AI BOX; Temperature: -40°C to 85°C
C86 C105-C110 C112-C116 = CC: SMD CAP Ceramic 100nF-10V-10%-X5R;0201; Manufacturer: YAGEO; Manufacturer Part Number: CC0201KRX5R6BB104; PN: 302010271; Package Size: 0201; Part Type: Ceramic; Rating: 10V,X5R; Status: ODYSSEY-i.MX8M; Temperature: -55°C to 85°C
C87 = CC: SMD CAP Ceramic 1uF-10V-10%-X5R;0402; Manufacturer: YAGEO; Manufacturer Part Number: CC0402KRX5R6BB105; PN: 302010040; Package Size: 0402; Part Type: Ceramic; Rating: 10V,X5R; Status: BeagleBone Carrier Board; Temperature: -55°C to 85°C
C135 = CC: SMD CAP Ceramic 1nF-2kV-10%-X7R;1206; ASSY: DNP; Manufacturer: YAGEO; Manufacturer Part Number: CC1206KKX7RDBB102; PN: 302011962; Part Type: Ceramic; Rating: 2KV,X7R; Status: Zola_Gateway; Temperature: -55°C to 125°C
C136 = CC: SMD CAP Ceramic 1nF-2kV-10%-X7R;1206; Manufacturer: YAGEO; Manufacturer Part Number: CC1206KKX7RDBB102; PN: 302011962; Part Type: Ceramic; Rating: 2KV,X7R; Status: Zola_Gateway; Temperature: -55°C to 125°C
C503 = CC: SMD CAP Ceramic 10uF-10V-10%-X5R;0603; Manufacturer: YAGEO; Manufacturer Part Number: CC0603KRX5R6BB106; PN: 302010103; Part Type: Ceramic; Rating: 10V,X5R; SIGNAL_MODEL: DEFAULT_CAPACITOR_4.7e+06pF_1_2; Status: BeagleBone Carrier Board; Temperature: -55°C to 85°C
D53-D60 D64 = DIODE_TVS_BI-DIR: SMD Diode ESD 0.05pF;0402; Manufacturer: SEMITEL; PN: 304060074; Package Size: 0402; Rating: 5V; Status: BeagleBone Carrier Board; Temperature: -40°C to 90°C
D63 = D: SMD Diode Schottky 30V-200mA;SOD-523; Manufacturer: LRC; PN: 304011072; Package Size: SOD-523; Rating: 30V; Status: 替代料; Temperature: -40°C to 125°C
F2 = Fuse: SMD PPTC;100mA-15V;0603; Manufacturer: Bourns; Manufacturer Part Number: MF-FSMF010X; PN: 307010054; Package Size: 0603; Rating: DC15V; Status: Jetson Nano Cluster; Temperature: -40°C to 85°C
J9 = HDMI_Type_A_19P_320010999: DIP HDMI TYPE A;19+4P-7.8*23.1*16.4mm-90D; Manufacturer: SUNGTECH; Manufacturer Part Number: ST-HD-001C; PN: 320010999; Package Size: 23.1 x 7.7mm; Status: reComputer CM4; Temperature: -20°C to 85°C
J24 = FPC_22+4P: SMD FPC CONN;22P-0.5mm;L16.7*W3.3*H3.95mm; Manufacturer: MTCONN; PN: 320060925; Package Size: 22P-0.50mm; Status: BeagleY AI; Temperature: -40°C to 85°C
R130 = R: SMD RES 0R-5%-1/4W;1206; Manufacturer: YAGEO; Manufacturer Part Number: RC1206JR-070RL; PN: 301010407; Part Type: RES; Rating: 5%; Status: Sensecap Gateway V1; Temperature: -55°C to 155°C
R131 = R: SMD RES 0R-5%-1/4W;1206; ASSY: DNP; Manufacturer: YAGEO; Manufacturer Part Number: RC1206JR-070RL; PN: 301010407; Part Type: RES; Rating: 5%; Status: Sensecap Gateway V1; Temperature: -55°C to 155°C
U8-U10 = TPD4E05U06DQAR: SMD Diode Array ESD;4 Channel,6 Gbps,5.5V;USON-10; Manufacturer: TI; PN: 304060294; Part Type: ESD; Priority: A; Rating: 5.5V; Status: BeagleBone AI TDA4VM; Temperature: -40°C to 125°C
C92 = CC: SMD CAP Ceramic 1uF-10V-10%-X5R;0402; CLASS: DISCRETE; Dielectric Type: Ceramic; Manufacturer: YAGEO; Manufacturer PN: CC0603MRX5R6BB226; Manufacturer Part Number: CC0402KRX5R6BB105; PN: 302010040; Package Size: 0402; Part Type: Ceramic; Rating: 10V,X5R; Status: BeagleBone Carrier Board; Temperature: -55°C to 85°C; Temperature Coefficient: X5R; Tolerance: 20%
C95 C97 = CC: SMD CAP Ceramic 1uF-10V-10%-X5R;0402; ASSY: DNP; CLASS: DISCRETE; Dielectric Type: Ceramic; Manufacturer: YAGEO; Manufacturer PN: CC0603MRX5R6BB226; Manufacturer Part Number: CC0402KRX5R6BB105; PN: 302010040; Package Size: 0402; Part Type: Ceramic; Rating: 10V,X5R; Status: BeagleBone Carrier Board; Temperature: -55°C to 85°C; Temperature Coefficient: X5R; Tolerance: 20%
C96 = CC: SMD CAP Ceramic 100nF-10V-10%-X5R;0201; ASSY: DNP; CLASS: DISCRETE; Company Part Status: BeagleBone Carrier Board; Dielectric Type: Ceramic; Manufacturer: YAGEO; Manufacturer PN: CC0402KRX7R8BB104; Manufacturer Part Number: CC0201KRX5R6BB104; PN: 302010271; Package Size: 0201; Part Type: Ceramic; Rating: 10V,X5R; SIGNAL_MODEL: DEFAULT_CAPACITOR_100000pF_1_2; Status: ODYSSEY-i.MX8M; Temperature: -55°C to 85°C; Temperature Coefficient: X7R; Tolerance: 10%
D24 D25 = D: SMD Diode Schottky 40V-1A;SOD-323; CLASS: DISCRETE; Company Part Status: BeagleBone Carrier Board; Manufacturer: CJ; Manufacturer PN: B5818WS SK; PN: 304011053; Package Size: SOD-323F; Part Type: Schottky Diode; Peak Forward Current: 1A; Rating: 40V; Repetitive Reverse Voltage Maximum: 30V; Status: reTerminal DM
D26 = D: SMD Diode Schottky 40V-500mA;SOD-123; Manufacturer: CJ; PN: 304020012; Part Type: Diode; Rating: 40V/0.5A; Status: Sensecap one; Temperature: -55°C to 150℃
J11 = USB2.0_Type_C_16+4P-Vert: SMD USB Type-C-Vertical;14+4P-L14*W3.66*H8.94mm; Manufacturer: MTCONN; PN: 320011080; Package Size: 14 x 3.66 mm; Status: CM4 EVB
R91 = R: SMD RES 0R-±1%-1/20W;0201; CLASS: DISCRETE; Company Part Status: BeagleBone Carrier Board; Manufacturer: YAGEO; Manufacturer PN: RC0402JR-070RL; Manufacturer Part Number: RC0201FR-070RL; PN: 301010525; Package Size: 0201; Part Type: RES; Rated Power: 1/16W; Rating: 1%; SIGNAL_MODEL: DEFAULT_RESISTOR_0.001OHM_1_2; Status: BeagleBone AI TDA4VM; Temperature: -55°C to 125°C; Datasheet: Y:\01_Cadence_Library\05_Datasheet\301010000_YAGEO_RC0402JR-070RL_Datasheet.pdf
R94 R95 = R: SMD RES 5.1K-5%-1/16W;0402; CLASS: DISCRETE; Company Part Status: Grove AI HAT for Edge Computing; Manufacturer: YAGEO; Manufacturer PN: RC0402JR-075K1L; Manufacturer Part Number: RC0402JR-075K1L; PN: 301010017; Package Size: 0402; Part Type: RES; Rated Power: 1/16W; Rating: 5%; Status: Grove AI HAT for Edge Computing; Temperature: -55°C to 155°C
R96 = R: SMD RES 1K-5%-1/10W;0603; ASSY: DNP; Manufacturer: YAGEO; Manufacturer Part Number: RC0603JR-071KL; PN: 301010291; Rating: 5%; Temperature: -55°C to 155°C
R97 R108-R111 = R: SMD RES 0R-±1%-1/20W;0201; Manufacturer: YAGEO; Manufacturer Part Number: RC0201FR-070RL; PN: 301010525; Package Size: 0201; Part Type: RES; Rating: 1%; Status: BeagleBone AI TDA4VM; Temperature: -55°C to 125°C; Datasheet: Y:\01_Cadence_Library\05_Datasheet\301010000_YAGEO_RC0402JR-070RL_Datasheet.pdf
R98 = R: SMD RES;4.7K-5%-1/20W;0201; ASSY: DNP; Manufacturer: YAGEO; Manufacturer Part Number: RC0201JR-074K7L; PN: 301010677; Package Size: 0201; Part Type: RES; Rating: 5%; Status: BeagleV-Ahead; Temperature: -55°C to 125°C
R100 = R: SMD RES;33R-5%-1/20W;0201; Manufacturer: YAGEO; Manufacturer Part Number: RC0201JR-0733RL; PN: 301010675; Package Size: 0201; Part Type: RES; Rating: 5%; Status: BeagleBone AI TDA4VM; Temperature: -55°C to 125°C; Datasheet: Y:\01_Cadence_Library\05_Datasheet\301010000_YAGEO_RC0402JR-070RL_Datasheet.pdf
R530 R531 = R: SMD RES 22R-5%-1/20W;0201; Manufacturer: YAGEO; Manufacturer Part Number: RC0201JR-0722RL; PN: 301010789; Package Size: 0201; Part Type: RES; Rating: 5%; Status: BeagleBone AI TDA4VM; Temperature: -55°C to 125°C
TP20-TP31 = Test_Point: Test Point;TP35S_SMD; CLASS: DISCRETE; Company Part Status: Mini-Gateway; Status: Mini-Gateway
U13 = LDO_3P: SMD IC PMIC;LDO-3.3V-200mA;SOT-23; ASSY: DNP; Manufacturer: Torex; PN: 310030099; Part Type: LDO; Status: ST; Temperature: -40°C to 85°C
U14 = SGM7222: SMD IC Analog Switch;High Speed USB 2.0 (480Mbps) DPDT Analog Switch;WQFN-10; Manufacturer: SGMICRO; PN: 310100627; Part Type: Analog Switch; Priority: A; Status: reComputer Jetson; Temperature: -40°C to 85°C
U15 = CH343P: SMD IC Interface USB to High Speed TTL;QFN16; Manufacturer: WCH; PN: 310071431; Part Type: IC; Status: reTerminal Plus; Temperature: -40°C to 85°C
C102 = CC: SMD CAP Ceramic 18pF-50V-5%-NPO;0201; ASSY: DNP; CLASS: DISCRETE; Company Part Status: BeagleBone Carrier Board; Dielectric Type: Ceramic; Manufacturer: Murata; Manufacturer PN: CC0402JRNPO9BN180; Manufacturer Part Number: GRM0335C1H180JA01D; PN: 302010406; Package Size: 0201; Part Type: Ceramic; Rating: 50V,NPO; Status: SenseCAP Tracker; Temperature: -55°C to 125°C; Temperature Coefficient: NPO; Tolerance: 5%
C103 = CC: SMD CAP Ceramic 18pF-50V-5%-NPO;0201; CLASS: DISCRETE; Company Part Status: BeagleBone Carrier Board; Dielectric Type: Ceramic; Manufacturer: Murata; Manufacturer PN: CC0402JRNPO9BN220; Manufacturer Part Number: GRM0335C1H180JA01D; PN: 302010406; Package Size: 0201; Part Type: Ceramic; Rating: 50V,NPO; Status: SenseCAP Tracker; Temperature: -55°C to 125°C; Temperature Coefficient: NPO; Tolerance: 5%
C104 = CC: SMD CAP Ceramic 1uF-10V-10%-X5R;0402; ASSY: DNP; Manufacturer: YAGEO; Manufacturer Part Number: CC0402KRX5R6BB105; PN: 302010040; Part Type: Ceramic; Rating: 10V,X5R; Status: BeagleBone Carrier Board; Temperature: -55°C to 85°C
D27 D29 = D: SMD Diode Schottky 40V-1A;SOD-323; Manufacturer: CJ; PN: 304011053; Part Type: Schottky Diode; Rating: 40V; Status: reTerminal DM
J12 = Header_1x2: DIP Beige Male Header VERT;1*2P-1.25MM; Manufacturer: 思拓展; Manufacturer Part Number: WY-3739; PN: 320020839; Part Type: Header; Status: Seeed BeagleBone Green Gateway; Temperature: -40°C to 85°C
J13 = Header_2x7_13P: SMD Black Male Header VERT;With Positioning,Without Pin14;2*7P-1.27-5.5-4.0mm; Manufacturer: 思拓展; Manufacturer Part Number: SF-PH-127-0030-2*7-K14-D; PN: 320021939; Package Size: 2*7P-1.27-5.5-4.0mm; Status: reComputer Industrial J201; Temperature: -40°C to 105°C
R101 = R: SMD RES 1M-5%-1/20W;0201; ASSY: DNP; CLASS: DISCRETE; Company Part Status: BeagleBone Carrier Board; Manufacturer: YAGEO; Manufacturer PN: RC0402FR-071ML; Manufacturer Part Number: RC0201JR-071ML; PN: 301010676; Package Size: 0201; Part Type: RES; Rated Power: 1/16W; Rating: 5%; Status: BeagleV-Ahead; Temperature: -55°C to 155°C
R104 R105 = R: SMD RES 510K-1%-1/16W;0402; Manufacturer: YAGEO; Manufacturer Part Number: RC0402FR-07510KL; PN: 301012003; Part Type: RES; Rating: 1%; Status: Sensecap Gateway V3; Temperature: -55°C to 155°C
U16 = DS1337: SMD IC Clock/Timing;SOIC-8; Manufacturer: NXP; PN: 310110015; Package Size: SOIC-8; Status: R2_CM4; Temperature: -40°C to 85°C
U17 = CAT24C256: SMD IC Memory;SOIC-8; Manufacturer: Microchip; PN: 310090011; Package Size: SOIC-8; Status: reTerminal DM; Temperature: -40°C to 85°C
U18 = SN74LVC1G07DCK: SMD IC Logic;TSSOP-5; Manufacturer: NXP; PN: 310050830; Part Type: Buffer; Status: ST; Temperature: -40°C to 125°C
U19 = ATECC608A: SMD IC AUTHENTICATION CHIP;8-UFDFN; CLASS: IC; Company Part Status: RE_CM4; Manufacturer: Microchip Technology; PN: 310990597; Package Size: 8-UFDFN; Part Type: Secure; Status: R2-M4_V1.0; Temperature: -40°C to 85°C
X3 = XTAL_2P: SMD Crystal 32.768KHz-12.5pF-20ppm;2P-L3.2*W1.5*H0.75mm; CLASS: DISCRETE; Frequency Tolerance: 20 ppm; Manufacturer: KDS; Manufacturer PN: DST310S; Manufacturer Part Number: DST310S; PN: 306011264; Package Size: 3.2 x 1.5 x 0.9mm; Part Type: Crystal; Rating: 20ppm; Status: reTerminal DM; Temperature: -40°C to 85°C
C120 = CC: SMD CAP Ceramic 100nF-10V-10%-X5R;0201; Manufacturer: YAGEO; Manufacturer Part Number: CC0201KRX5R6BB104; PN: 302010271; Package Size: 0201; Part Type: Ceramic; Rating: 10V,X5R; SIGNAL_MODEL: DEFAULT_CAPACITOR_100000pF_1_2; Status: ODYSSEY-i.MX8M; Temperature: -55°C to 85°C
C121-C123 C128 = CC: SMD CAP Ceramic 33pF-50V-5%-NPO;0201; Manufacturer: YAGEO; Manufacturer Part Number: CC0201JRNPO9BN330; PN: 302010741; Package Size: 0201; Part Type: Ceramic; Rating: 50V,NPO; SIGNAL_MODEL: DEFAULT_CAPACITOR_33.000000pF_1_2; Status: BeagleBone AI TDA4VM; Temperature: -55°C to 125°C
C126 C127 = CT: SMD CAP Tantalum 47uF-10V;B; Manufacturer: AVX; Manufacturer Part Number: TAJB476K010RNJ; PN: 302020020; Part Type: Tantalum; Rating: 10V,Tantalum; Status: BeagleBone Carrier Board
D30-D33 = DIODE_TVS_BI-DIR: SMD TVS DIODE 3.6V-6.4V-1pF;X1SON(2); Manufacturer: TI; Manufacturer Part Number: TPD1E1B04DPYR/T; PN: 304050798; Part Type: ESD; Rating: 3.6V; Status: Grove Base Cape for PocketBeagle; Temperature: -40°C to 125°C
J14 J15 = MINI_PCIE_52P: SMD Mini PCI-E CONN;52P-0.8mm-L29.9*9.0*9.0mm; CLASS: IO; Company Part Status: R2; Manufacturer: 商祺; PN: 320991284; Package Size: 52P-0.8-L29.9*W8.2*H4mm; Part Type: PCIE Connector; Status: reTerminal Plus; Temperature: -55°C to 85°C
J16 = Nano_SIM_Hloder_ST-SIM-N032: SMD Nano-SIM Holder;7P+4-L14.0*W12.0*H1.40mm(掀盖); Manufacturer: 山旗; PN: 320100310; Rating: Nano 掀盖; Status: LTE_Add-on_Board; Temperature: -30°C to 80°C
MH6 MH10 = MHole: SMD Stud; M2.0 Copper pillar , D5.56*6.6mm; Manufacturer: 雄和远景; PN: TMP-565; Package Size: D5.56 mm; Status: reComputer R1002; Temperature: - 40 °C to 85 °C
R113 R116 = R: SMD RES 0R-5%-1/8W;0805; Manufacturer: YAGEO; Manufacturer Part Number: RC0805JR-070RL; PN: 301010359; Part Type: RES; Rating: 5%; Status: Sensecap Gateway V1; Temperature: -55°C to 155°C
R114 = R: SMD RES 10K-±1%-1/20W;0201; Manufacturer: YAGEO; Manufacturer Part Number: RC0201FR-0710KL; PN: 301010526; Package Size: 0201; Part Type: RES; Rating: 1%; Status: BeagleBone AI TDA4VM; Temperature: -55°C to 125°C
R115 = R: SMD RES 15K-1%-1/20W;0201; Manufacturer: YAGEO; Manufacturer Part Number: RC0201FR-0715KL; PN: 301012913; Package Size: 0201; Part Type: RES; Rating: 1%; Status: AM62_OSM; Temperature: -55°C to 125°C
U21 = LDO_3P: SMD IC PMIC;LDO-1.8V-80mA;SOT-23; Manufacturer: Torex; PN: 310030016; Package Size: SOT-23; Status: BeagleBone Carrier Board

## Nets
5V_TYPC: C92.1 C93.1 C94.1 C95.1 C96.1 C99.2 D21.2 J11.A4(A4/VBUS) J11.A9(A9/VBUS) J11.B4(B4/VBUS) J11.B9(B9/VBUS) TP20.1(TP) U13.3(Vin) U15.3(VDD5) U15.9(VBUS) ; also on sheet 6
+1.8V_OUT: R112.2 ; also on sheet 6
GND: C58.2 C59.2 C60.2 C61.2 C62.2 C63.2 C64.2 C65.2 C66.2 C67.2 C68.2 C69.1 C70.1 C71.1 C72.1 C73.2 C74.2 C75.2 C76.1 C77.2 C78.1 C79.2 C80.2 C81.2 C82.2 C83.2 C84.2 C85.2 C86.2 C87.2 C92.2 C93.2 C94.2 C95.2 C96.2 C97.2 C98.2 C99.1 C100.1 C101.1 C102.1 C103.2 C104.2 C105.2 C106.2 C107.2 C108.2 C110.1 C111.2 C112.1 C113.1 C114.1 C115.1 C116.1 C117.2 C118.2 C119.2 C120.2 C121.2 C122.2 C123.2 C124.2 C125.2 C126.2 C127.2 C128.2 C136.1 C503.2 C504.2 D14.1 D15.1 D16.1 D17.1 D18.1 D19.1 D20.1 D21.1 D22.1 D23.1 D28.1 D30.1 D31.1 D32.1 D33.1 D53.1 D54.1 D55.1 D56.1 D57.1 D58.1 D59.1 D60.1 D64.1 J9.2(D2GND) J9.5(D1GND) J9.8(D0GND) J9.11(CKGND) J9.14(Utility) J9.17(DDCGND) J11.A1(A1/GND) J11.A12(A12/GND) J11.B1(B1/GND) J11.B12(B12/GND) J12.1 J13.8 J14.4 J14.9 J14.15 J14.18 J14.21 J14.26 J14.27 J14.29 J14.34 J14.35 J14.37 J14.40 J14.43 J14.50 J14.53 J14.54 J15.9 J15.15 J15.18 J15.21 J15.26 J15.27 J15.29 J15.34 J15.35 J15.37 J15.40 J15.43 J15.50 J15.53 J15.54 J16.C5(GND) J16.G1(GND1) J16.G2(GND2) J16.G3(GND3) J24.1 J24.4 J24.7 J24.10 J24.13 J24.16 J24.19 J24.SH1 J24.SH2 J24.SH3 J24.SH4 MH6.1(NC) MH10.1(NC) R53.1 R54.1 R55.1 R56.1 R57.2 R58.2 R72.2 R73.2 R74.1 R75.1 R94.2 R95.2 R96.2 R97.2 R108.2 R130.1 R632.2 R633.2 U5.37(VSS_PAD) U6.1(GND) U7.6(GNG) U8.3(GND1) U8.8(GND2) U9.3(GND1) U9.8(GND2) U10.3(GND1) U10.8(GND2) U13.1(Vss) U14.4(GND) U15.2(GND) U15.17(EP) U16.4(GND) U17.1(A0) U17.2(A1) U17.3(A2) U17.4(VSS) U18.3(GND) U19.4(GND) U19.9(PAD) U21.1(Vss) X2.2 X2.4 ; also on sheet 4 5 6 7 8 14 15 16 18
GND_EARTH: C135.2 J8.S1(BODY1) J8.S2(BODY2) J8.S3(BODY3) J8.S4(BODY4) J11.S1 J11.S2 J11.S3 J11.S4 R131.2 R632.1 R633.1 ; also on sheet 4 7 14 18
V3: C101.2 R91.2 U15.6(V3)
VCC_USB1: C76.2 C78.2 C82.1 C83.1 D16.2 FB5.1 U7.8(OUTA)
VCC_USB2: C77.1 C79.1 C84.1 C85.1 D17.2 FB6.2 U7.5(OUTB)
VDD33_HUB2: C59.1 C62.1 C63.1 C64.1 C65.1 C66.1 C67.1 C68.1 C73.1 FB4.2 R51.1 R52.1 R59.1 R60.2 R61.2 R62.2 R63.2 R65.2 R66.2 R67.2 R68.2 U5.5(VDD33_1) U5.10(VDD33_2) U5.15(VDD33_3) U5.23(VDD33_4) U5.29(VDD33_5) U5.36(VDD33_6) U6.4(VCC) ; also on sheet 8
VDD_3V3_SYS: C58.1 C106.1 C107.1 C110.2 C503.1 C504.1 D25.1(A) D27.1(A) FB4.1 FB26.2 J13.1 J13.7 R102.1 R113.1 R116.1 U17.8(VCC) U19.8(VCC) ; also on sheet 4 5 7 8 14 15 16 18
VDD_5V_SYS: C80.1 C81.1 C108.1 D63.1(A) R104.1 R105.1 U7.7(IN) U18.5(VCC) ; also on sheet 5 6
VDD_LTE_3V3: C111.1 C115.2 C124.1 C125.1 C126.1 C127.1 J15.2 J15.39 J15.41 J15.52 R116.2 TP31.1(TP) U21.3(Vin)
VDD_RTC: C104.1 C105.1 D27.2(C) D28.2 D29.2(C) TP22.1(TP) U16.8(VCC)
CAM0_C_N: D58.2 J24.8 ; also on sheet 6
CAM0_C_P: D59.2 J24.9 ; also on sheet 6
CAM0_D0_N: D53.2 J24.2 ; also on sheet 6
CAM0_D0_P: D55.2 J24.3 ; also on sheet 6
CAM0_D1_N: D56.2 J24.5 ; also on sheet 6
CAM0_D1_P: D57.2 J24.6 ; also on sheet 6
CAM_GPIO: D64.2 J24.17 ; also on sheet 6
CM4_IIC0_SCL: D60.2 J24.20 ; also on sheet 6
CM4_IIC0_SDA: D54.2 J24.21 ; also on sheet 6
CM4_IIC1_SCL: U19.6(SCL) ; also on sheet 6
CM4_IIC1_SDA: U19.5(SDA) ; also on sheet 6
CM4_IIC3_SCL: J14.30 ; also on sheet 6 15 18
CM4_IIC3_SDA: J14.32 ; also on sheet 6 15 18
CM4_IIC5_SCL: U16.6(SCL) U17.6(SCL) ; also on sheet 4 6
CM4_IIC5_SDA: U16.5(SDA) U17.5(SDA) ; also on sheet 4 6
CM4_SPI0_CE0: J13.9 ; also on sheet 6
CM4_SPI0_CE1: J14.51 ; also on sheet 6
CM4_SPI0_MISO: J13.11 J14.47 ; also on sheet 6
CM4_SPI0_MOSI: J13.12 J14.49 ; also on sheet 6
CM4_SPI0_SCLK: J13.10 R111.1 ; also on sheet 6
CM4_TPM_IRQ: J13.2 ; also on sheet 6
CM4_UART0_RXD: R100.2 ; also on sheet 6
CM4_UART0_TXD: D26.2(C) R99.2 ; also on sheet 6
EEPROM_WP: R103.2 ; also on sheet 18
GLOBAL_EN: U18.4(Y) ; also on sheet 6
HDMI0_5V: C86.1 C87.1 D20.2 F2.1 J9.18(+5V)
HDMI0_CEC: J9.13(CEC) U10.1(CH1) U10.10(NC1) ; also on sheet 6
HDMI0_CLK_N: L22.3 ; also on sheet 6
HDMI0_CLK_N1: J9.12(CK-) L22.4 U9.5(CH4) U9.6(NC4)
HDMI0_CLK_P: L22.2 ; also on sheet 6
HDMI0_CLK_P1: J9.10(CK+) L22.1 U9.4(CH3) U9.7(NC3)
HDMI0_HOTPLUG: J9.19(HPD) U10.2(CH2) U10.9(NC2) ; also on sheet 6
HDMI0_SCL: J9.15(SCL) U10.5(CH4) U10.6(NC4) ; also on sheet 6
HDMI0_SDA: J9.16(SDA) U10.4(CH3) U10.7(NC3) ; also on sheet 6
HDMI0_TX0_N: L21.3 ; also on sheet 6
HDMI0_TX0_N1: J9.9(D0-) L21.4 U9.2(CH2) U9.9(NC2)
HDMI0_TX0_P: L21.2 ; also on sheet 6
HDMI0_TX0_P1: J9.7(D0+) L21.1 U9.1(CH1) U9.10(NC1)
HDMI0_TX1_N: L20.3 ; also on sheet 6
HDMI0_TX1_N1: J9.6(D1-) L20.4 U8.5(CH4) U8.6(NC4)
HDMI0_TX1_P: L20.2 ; also on sheet 6
HDMI0_TX1_P1: J9.4(D1+) L20.1 U8.4(CH3) U8.7(NC3)
HDMI0_TX2_N: L19.3 ; also on sheet 6
HDMI0_TX2_N1: J9.3(D2-) L19.4 U8.2(CH2) U8.9(NC2)
HDMI0_TX2_P: L19.2 ; also on sheet 6
HDMI0_TX2_P1: J9.1(D2+) L19.1 U8.1(CH1) U8.10(NC1)
LORA_3V3: C112.2 C113.2 C114.2 C117.1 C118.1 C119.1 J14.2 J14.24 J14.39 J14.41 J14.52 R113.2 TP30.1(TP)
LoRaWAN_SX1262_CS: J14.25 ; also on sheet 18
LoRaWAN_SX1262_RST: J14.10 ; also on sheet 18
LoRaWAN_SX1302_RST: R110.2 ; also on sheet 18
LTE_LED_WWAN#: J15.42 ; also on sheet 7
LTE_RESET: R109.2 ; also on sheet 18
PCIE_USIM_PRESE: J15.44 J16.SW R114.2
RTC_INT: C109.1 R104.2 U16.3(~{INTA})
TPM_RST: J13.3 ; also on sheet 18
UART_3V3: C97.1 C100.2 D24.1(A) R91.1 R96.1 R98.1 TP21.1(TP) U13.2(Vout) U15.1(VIO)
USB1_RST: R64.1 ; also on sheet 8
USB2_RST: C61.1 R52.2 R59.2 R71.2 U5.26(RESET_N) U6.2(~{RESET})
USB2_RST_EN: R71.1 ; also on sheet 18
USB2_VBUS_EN1: R65.1 R75.2 U5.12(PRTPWR1/BC_EN1) U7.1(ENA)
USB2_VBUS_EN2: R66.1 R74.2 U5.16(PRTPWR2/BC_EN2) U7.4(ENB)
USB2_VRCURn1: R60.1 U5.13(OCSN1) U7.2(FLGA)
USB2_VRCURn2: R61.1 U5.17(OCSN2) U7.3(FLGB)
USB_1M: U14.6(D2-) ; also on sheet 7
USB_1P: U14.2(D2+) ; also on sheet 7
USB_C_DM: R530.2 U14.5(D-)
USB_C_DP: R531.2 U14.3(D+)
USB_DET: C60.1 R51.2 U5.27(VBUS_DET)
USB_HUB1_DM3: U5.30(DM_UP) ; also on sheet 8
USB_HUB1_DP3: U5.31(DP_UP) ; also on sheet 8
USB_HUB2_DM1: L4.4 U5.1(DN1)
USB_HUB2_DM2: L5.2 U5.3(DN2)
USB_HUB2_DM3: J14.36 U5.6(NC/DN3)
USB_HUB2_DM4: J15.36 U5.8(NC/DN4)
USB_HUB2_DP1: L4.1 U5.2(DP1)
USB_HUB2_DP2: L5.3 U5.4(DP2)
USB_HUB2_DP3: J14.38 U5.7(NC/DP3)
USB_HUB2_DP4: J15.38 U5.9(NC/DP4)
USB_OTG_ID: U14.10(S) ; also on sheet 6 7
USB_TO_UART_DM: U14.7(D1-) U15.8(UD-)
USB_TO_UART_DP: U14.1(D1+) U15.7(UD+)
USBA_GND: J8.A4(GND_A) J8.B4(GND_B) R72.1 R73.1
USBC_DM: D23.2 J11.A7(DN1) J11.B7(DN2) R530.1
USBC_DP: D22.2 J11.A6(DP1) J11.B6(DP2) R531.1
USIM_1V8: C116.2 R112.1 R114.1 TP29.1(TP) U21.2(Vout)
USIM_CLK: C123.1 D31.2 J15.12 J16.C3(CLK)
USIM_DATA: C122.1 D30.2 J15.10 J16.C7(I/O) R115.2
USIM_GND: J15.4 R108.1
USIM_RST: C128.1 D32.2 J15.14 J16.C2(RST)
USIM_VDD: C120.1 C121.1 D33.2 J15.8 J16.C1(VCC) R115.1
N21080778: C135.1 C136.2 J9.20(GND1) J9.21(GND2) J9.22(GND3) J9.23(GND4) R130.2 R131.1
N21083178: D29.1(A) J12.2 TP23.1(TP)
N21084468: C109.2 R105.2 U18.2(A)
N21149713: J14.14 TP25.1(TP)
N21149734: J14.16 TP26.1(TP)
N21149896: J14.31 TP27.1(TP)
N21149903: J14.33 TP28.1(TP)
N21150017: J14.45 R111.2
N21206327: C103.1 R101.2 U16.1(X1) X3.2
N21206924: C102.2 R101.1 U16.2(X2) X3.1
N21339151: J14.22 R110.1
N21339355: J15.22 R109.1
N22695835: J14.8 TP24.1(TP)
N22714565: R102.2 R103.1 U17.7(WP)
N23449459: J11.A5(CC1) R94.1
N23449477: J11.B5(CC2) R95.1
N23449775: C98.1 D24.2(C) D25.2(C) U14.9(VCC)
N23449933: D26.1(A) R98.2 R99.1 U15.5(RXD)
N23450082: R100.1 U15.4(TXD)
N23450096: R97.1 U14.8(~{OE})
N23451512: R53.2 U5.28(SUSP_IND/LOCAL_PWR/NON_REM0)
N23451530: R54.2 U5.22(SDA/SMBDATA/NON_REM1)
N23451550: R55.2 U5.24(SCL/SMBCLK/CFG_SEL0)
N23451563: R56.2 U5.25(HS_IND/CFG_SEL1)
N23451623: R57.1 U5.11(TEST)
N23451671: R58.1 U5.35(RBIAS)
N23451839: C69.2 C70.2 U5.34(PLLFILT)
N23451845: R62.1 U5.19(NC/OCSN3)
N23451875: C71.2 C72.2 U5.14(CRFILT)
N23451879: R63.1 U5.21(NC/OCSN4)
N23451944: R69.2 U5.32(XTALOUT)
N23451981: R67.1 U5.18(NC/PRTPWR3/BC_EN3)
N23452007: C75.1 R70.2 U5.33(XTALIN/CLKIN) X2.3
N23452009: R68.1 U5.20(NC/PRTPWR4/BC_EN4)
N23452027: C74.1 R69.1 R70.1 X2.1
N23452929: FB6.1 J8.B1(VBUS_B)
N23452966: D18.2 J8.B2(DM_B) L5.1
N23452985: D19.2 J8.B3(DP_B) L5.4
N23456906: R64.2 U6.3(~{MR})
N23711005: D15.2 J8.A2(DM_A) L4.3
N23711301: D14.2 J8.A3(DP_A) L4.2
N23869571: D63.2(C) F2.2
N23918848: FB26.1 J24.22
N23992927: FB5.2 J8.A1(VBUS_A)

Not connected (* = marked no-connect by the designer): J13 4* 5* 6* 13*; J14 1* 3* 5* 6* 7* 11* 12* 13* 17* 19* 20* 23* 28* 42* 44* 46* 48*; J15 1* 3* 5* 6* 7* 11* 13* 16* 17* 19* 20* 23* 24* 25* 28* 30* 31* 32* 33* 45* 46* 47* 48* 49* 51*; J16 C6(VPP)*; J24 11* 12* 14* 15* 18*; U15 10(~{ACT})* 11(~{DCD})* 12(~{DTR})* 13(~{RTS})* 14(~{DSR})* 15(~{CTS})* 16(~{RI})*; U16 7(SQW/~{INTB})*; U18 1(NC)*; U19 1(NC)* 2(NC)* 3(NC)* 7(NC_4)*

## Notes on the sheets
sheet 9
- USB2.0_HUB2
- Layout Note:
- USB_HUB2  POWER
- ALL USB Signals ：90R
- Imax=500mA
- Design Note:
- USB2_RST Delay USB1_RST 140 - 560ms
- DOUBLE_USB2.0_HOST_POWER
- DOUBLE_USB2.0_HOST
- Imax=500mA
- Imax=500mA
- Layout Note:
- GND Copper-laying
sheet 10
- Layout Note:
- HDMI 2.0
- ALL HMDI Signals ：100R and Isometric
- Pmax;5V0&0.05A
- CSI0
- Layout Note:
- ALL CSI Signals ：100R and Isometric
sheet 11
- TYPC_USB2.0
- Design Note:
- Debug or Program eMMC
- 200mA
- USB TO UART
- CM4 USB 2.0 SWITCH
- USB_OTG_ID
- Function
- 0
- UART
- 1
- TYPE-C Switch
sheet 12
- RTC_POWER
- Pmax;3.3V&0.05A
- RTC IC
- Design Note:
- CR2032 BAT
  PCB need to add +/-
- I2C address : 0x51
- TPM2.0
- EEPROM
- I2C address : 0x50
- encryption  Sensor
- ECC608 I2C Speed:
- 100KHz
- I2C address : 0xc0
sheet 13
- 3A
- 1A
- Design Note:
- SPI LoRa Module :(W1302)  HIGH RST.
  USB LoRa Module :(MCU)  LOW RST.
- Design Note:
- Design Note:
- LoRa Module: WM1302 SPI/USB Version
  Zigbee: USB Version
- LTE Module:  EC20/EC25
  LoRa Module: WM1302 USB Version
  Zigbee: USB Version
- 1A
- Close J14
- 3A
- Close J15
